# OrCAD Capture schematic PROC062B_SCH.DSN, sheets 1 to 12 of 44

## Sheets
1 44. HARDWARE SCHEMATICS: title: HARDWARE SCHEMATICS; rev: A
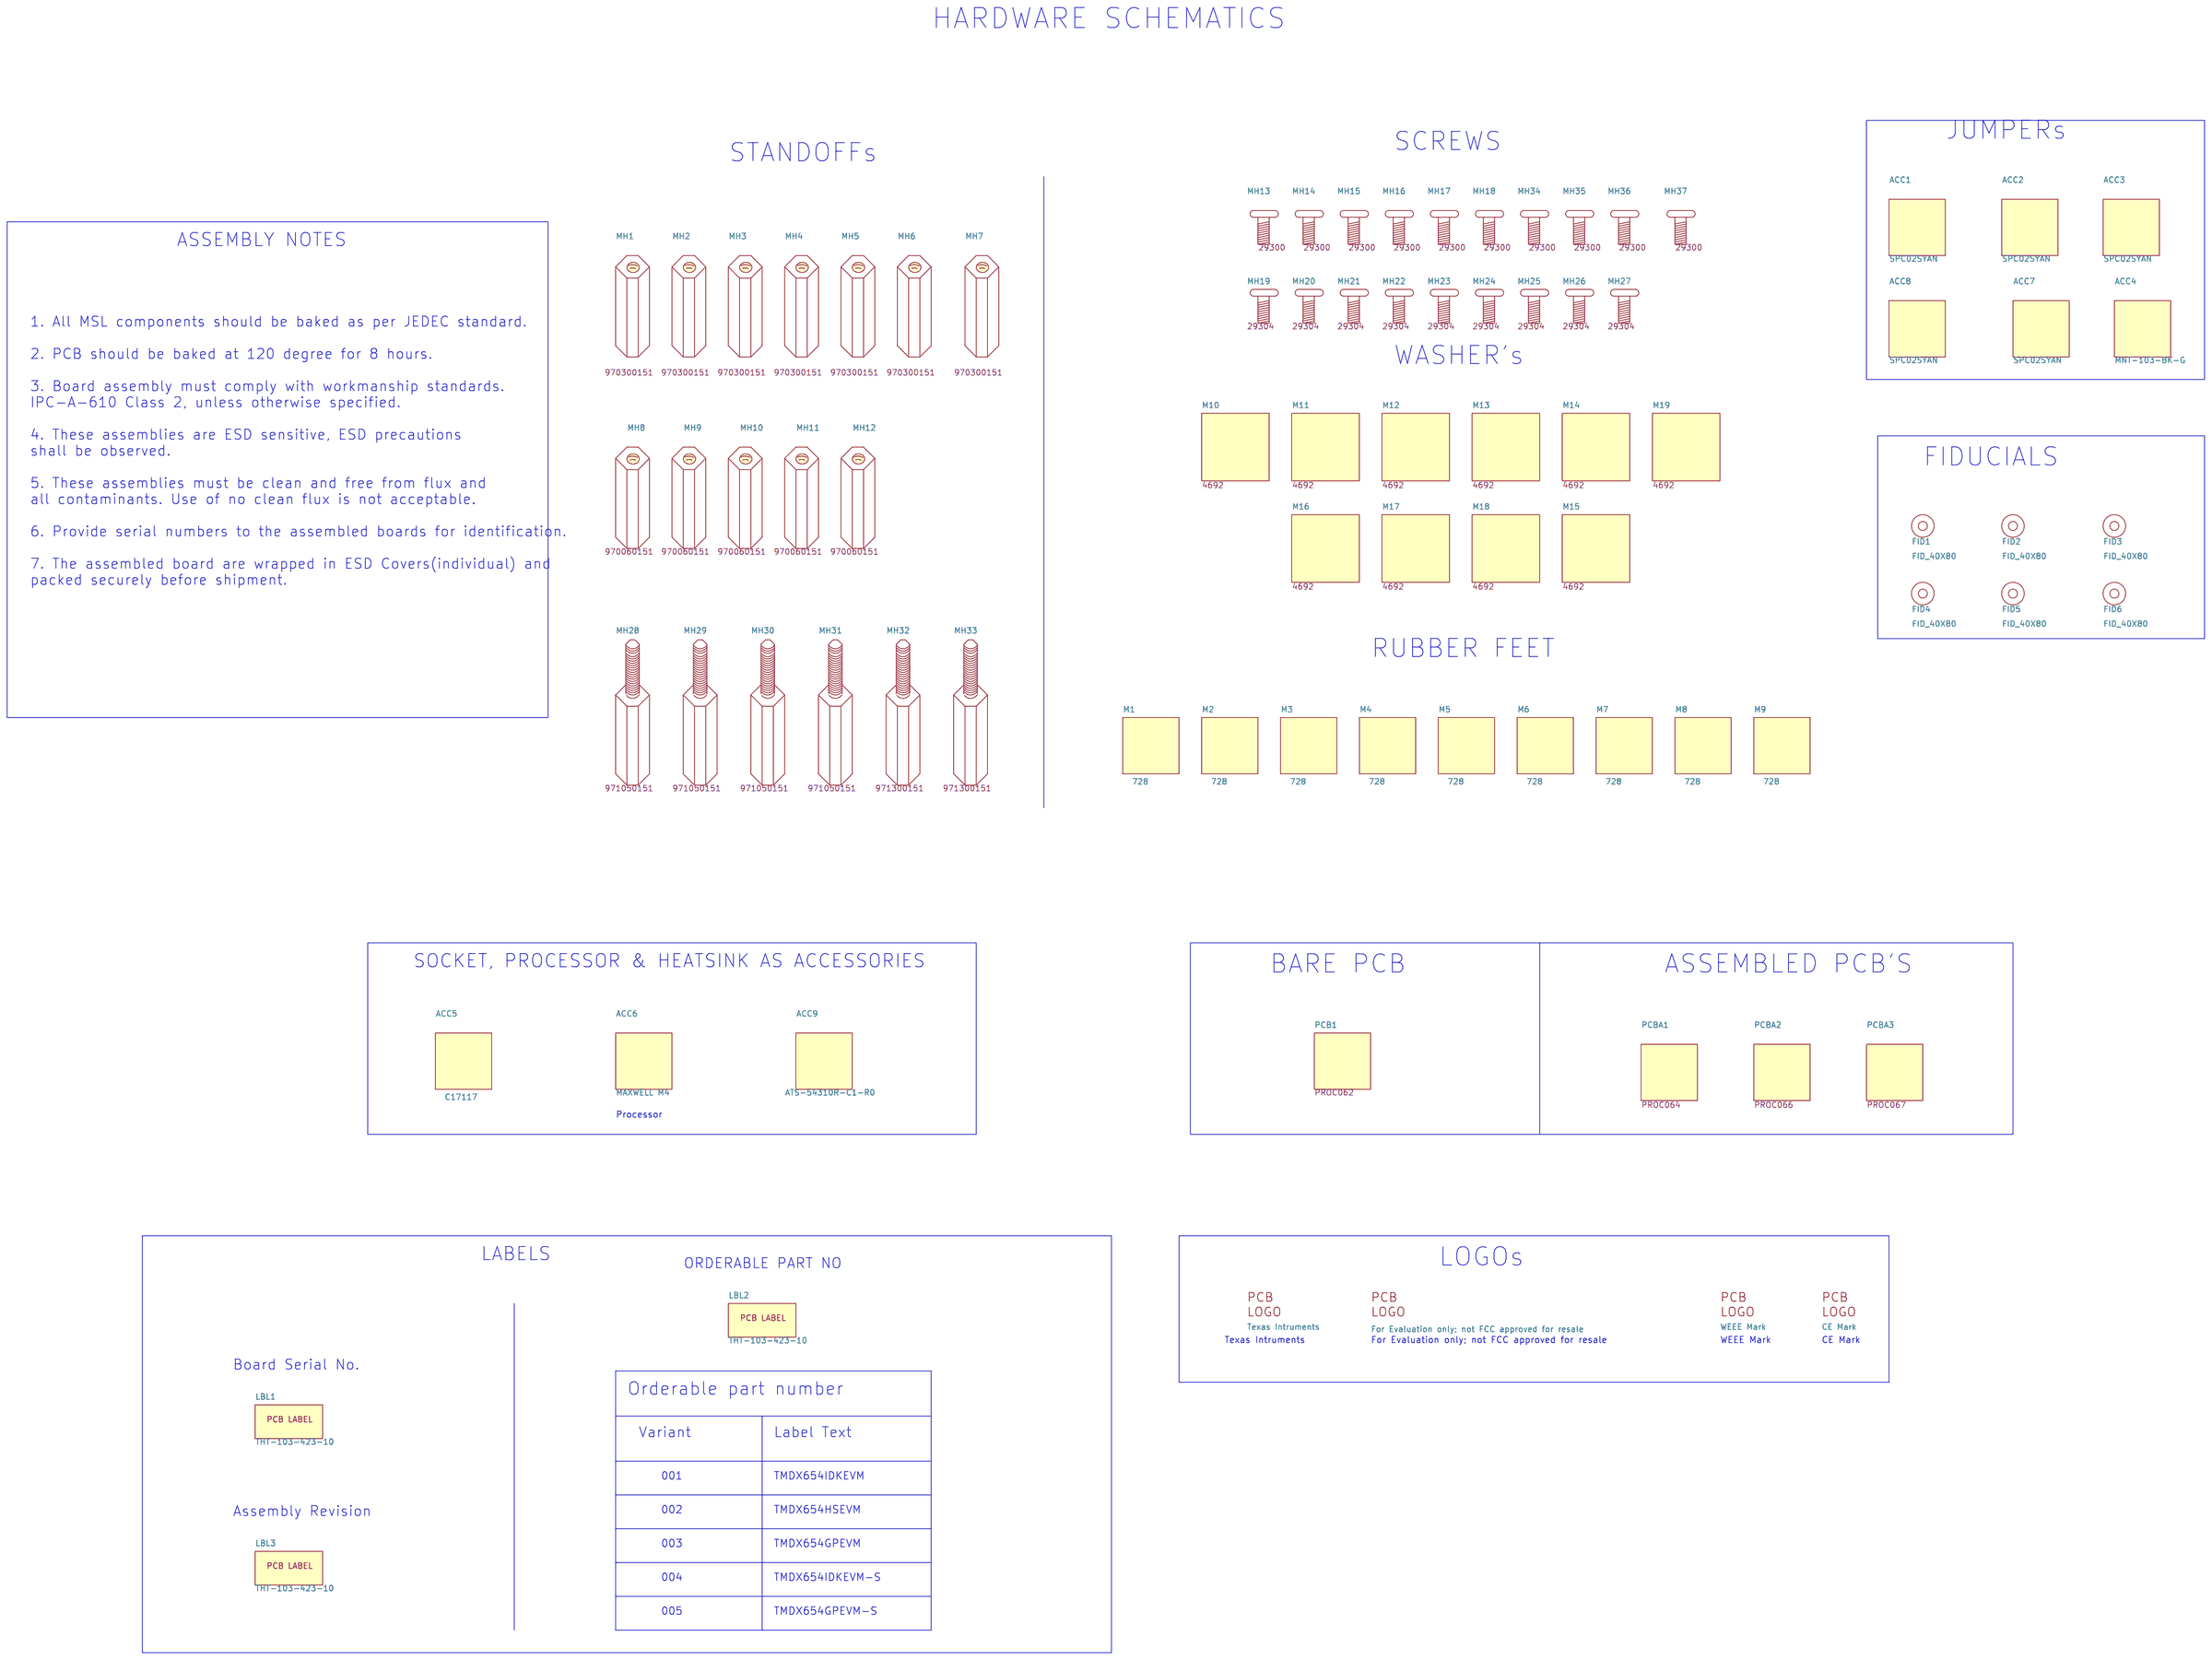
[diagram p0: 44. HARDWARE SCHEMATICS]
2 07. GPIO MAPPING TABLE: title: GPIO  MAPPING TABLE
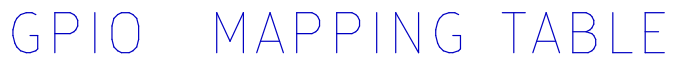
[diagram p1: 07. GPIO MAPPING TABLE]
3 04. BLOCK DIAGRAM_XDS110: title: BLOCK DIAGRAM_XDS110
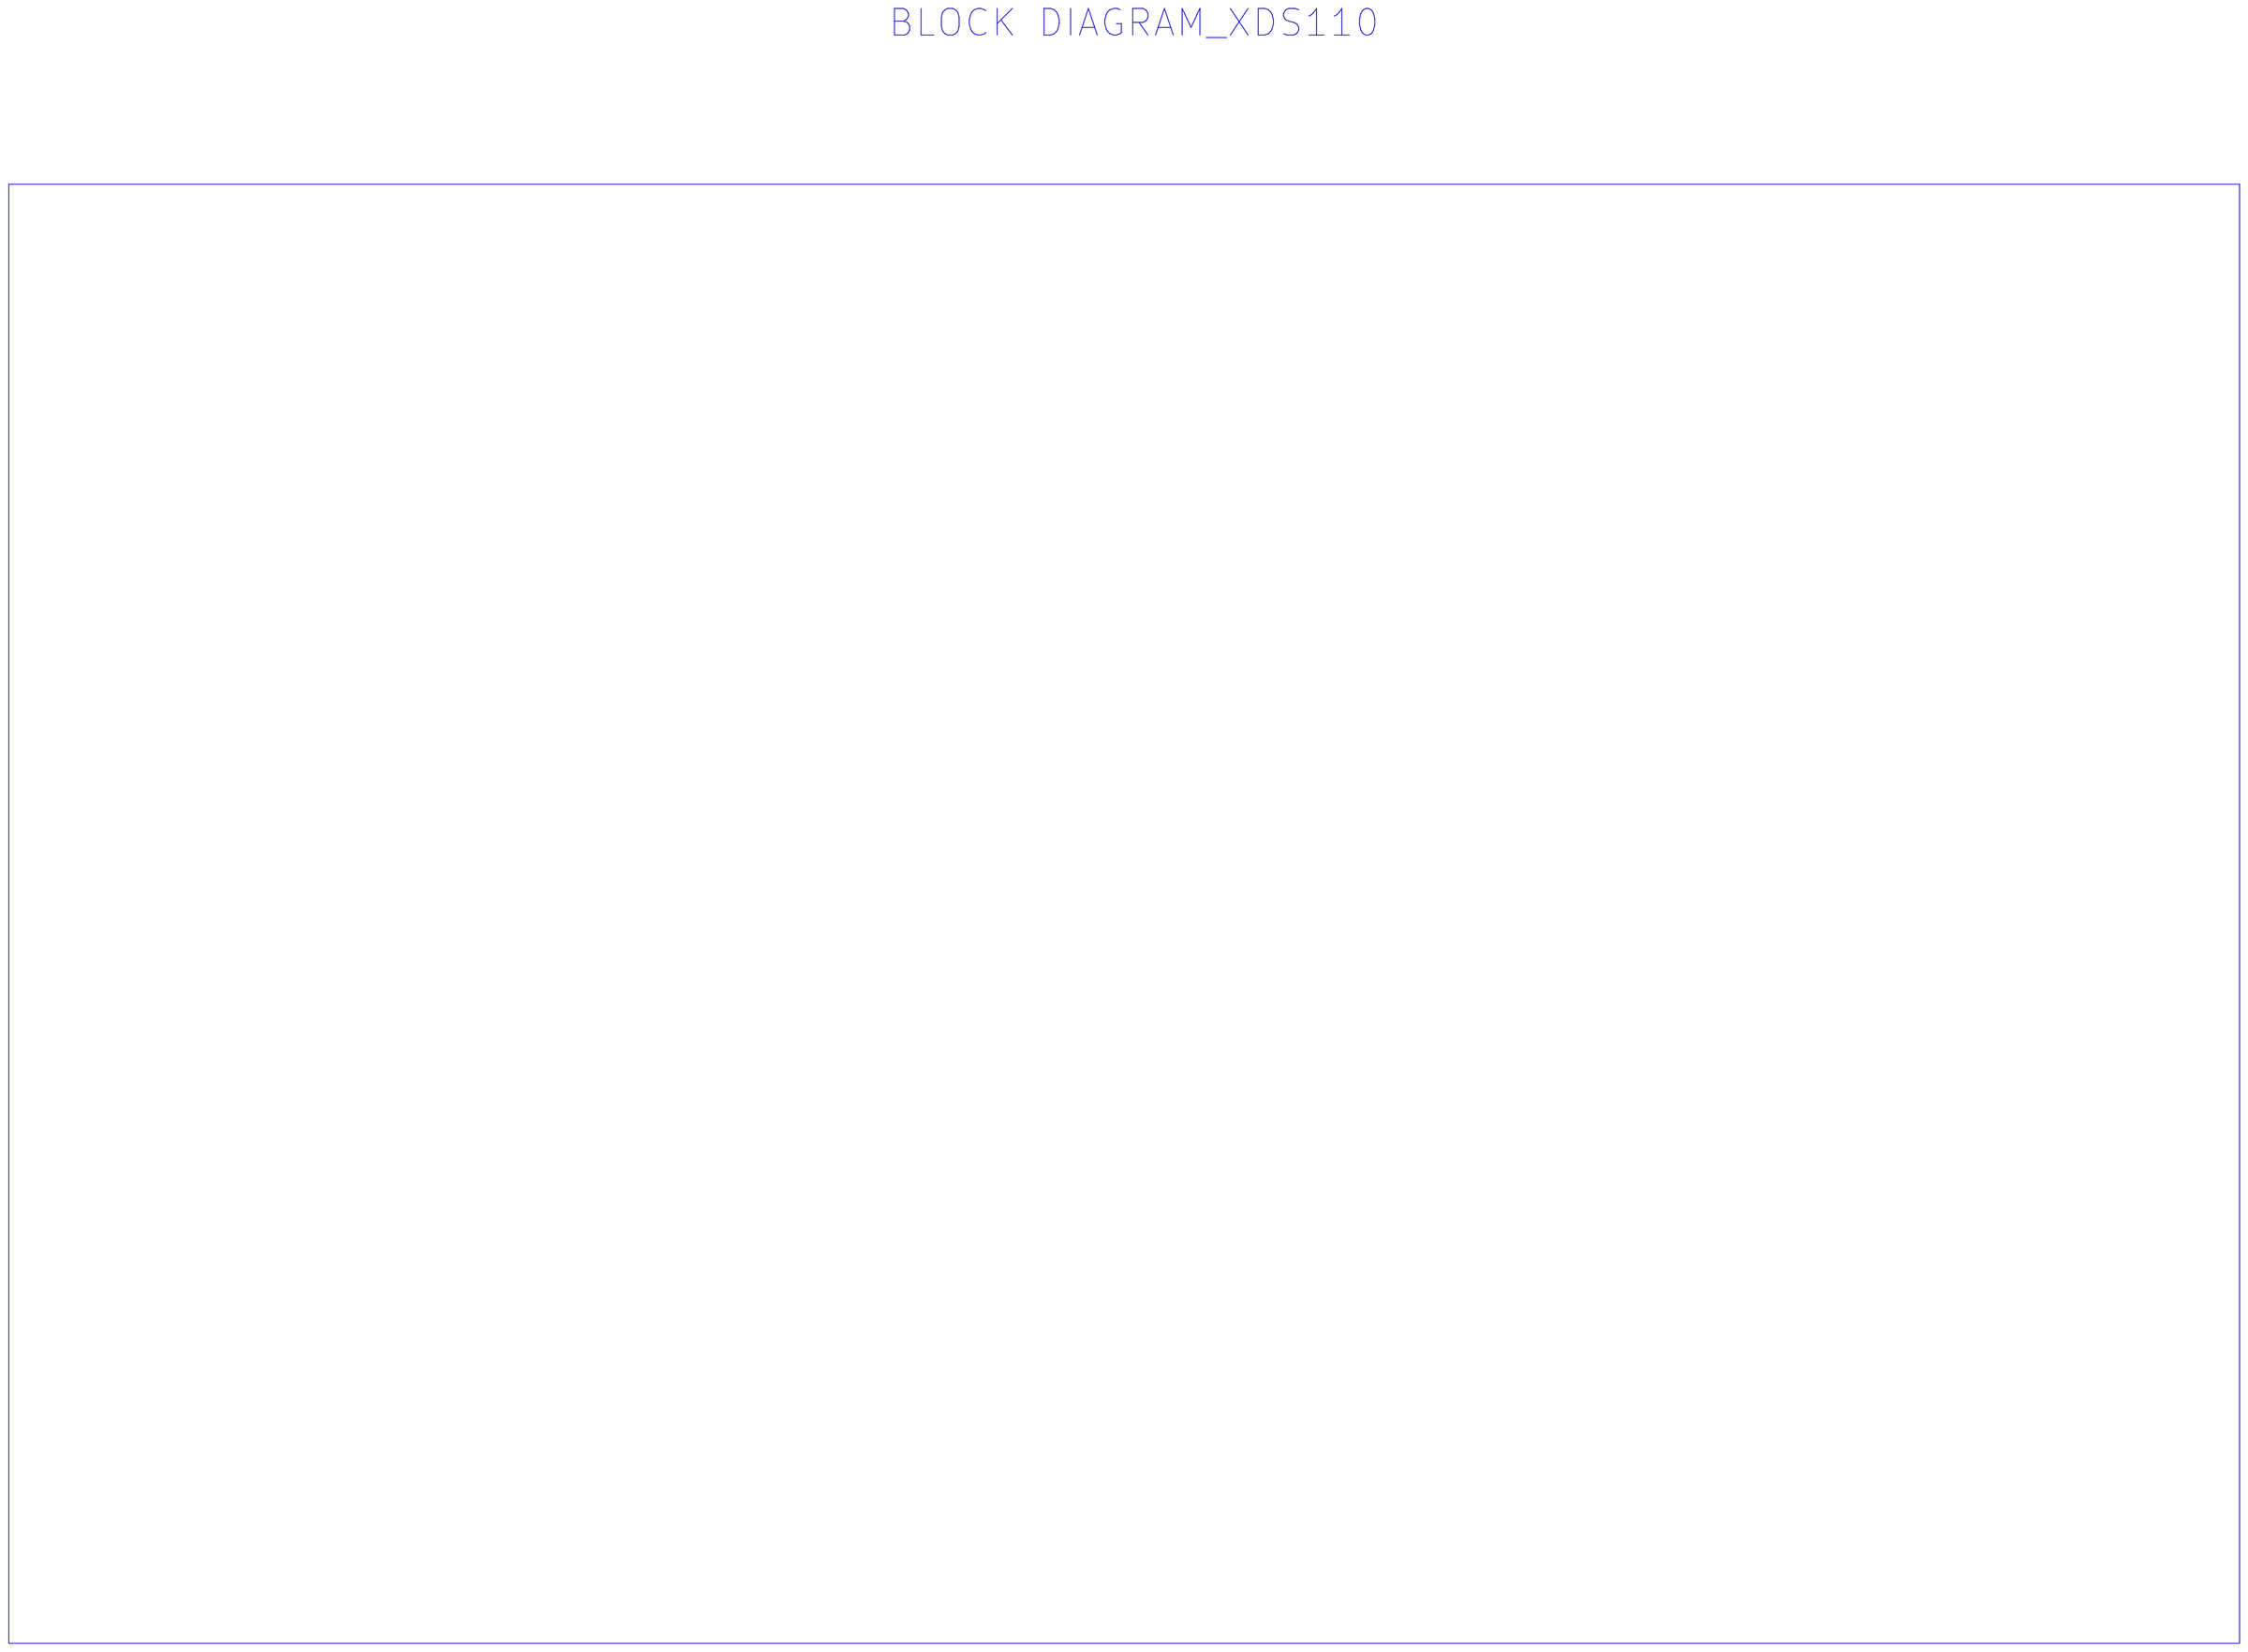
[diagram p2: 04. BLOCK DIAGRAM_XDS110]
4 09. SPI TREE: title: SPI TREE
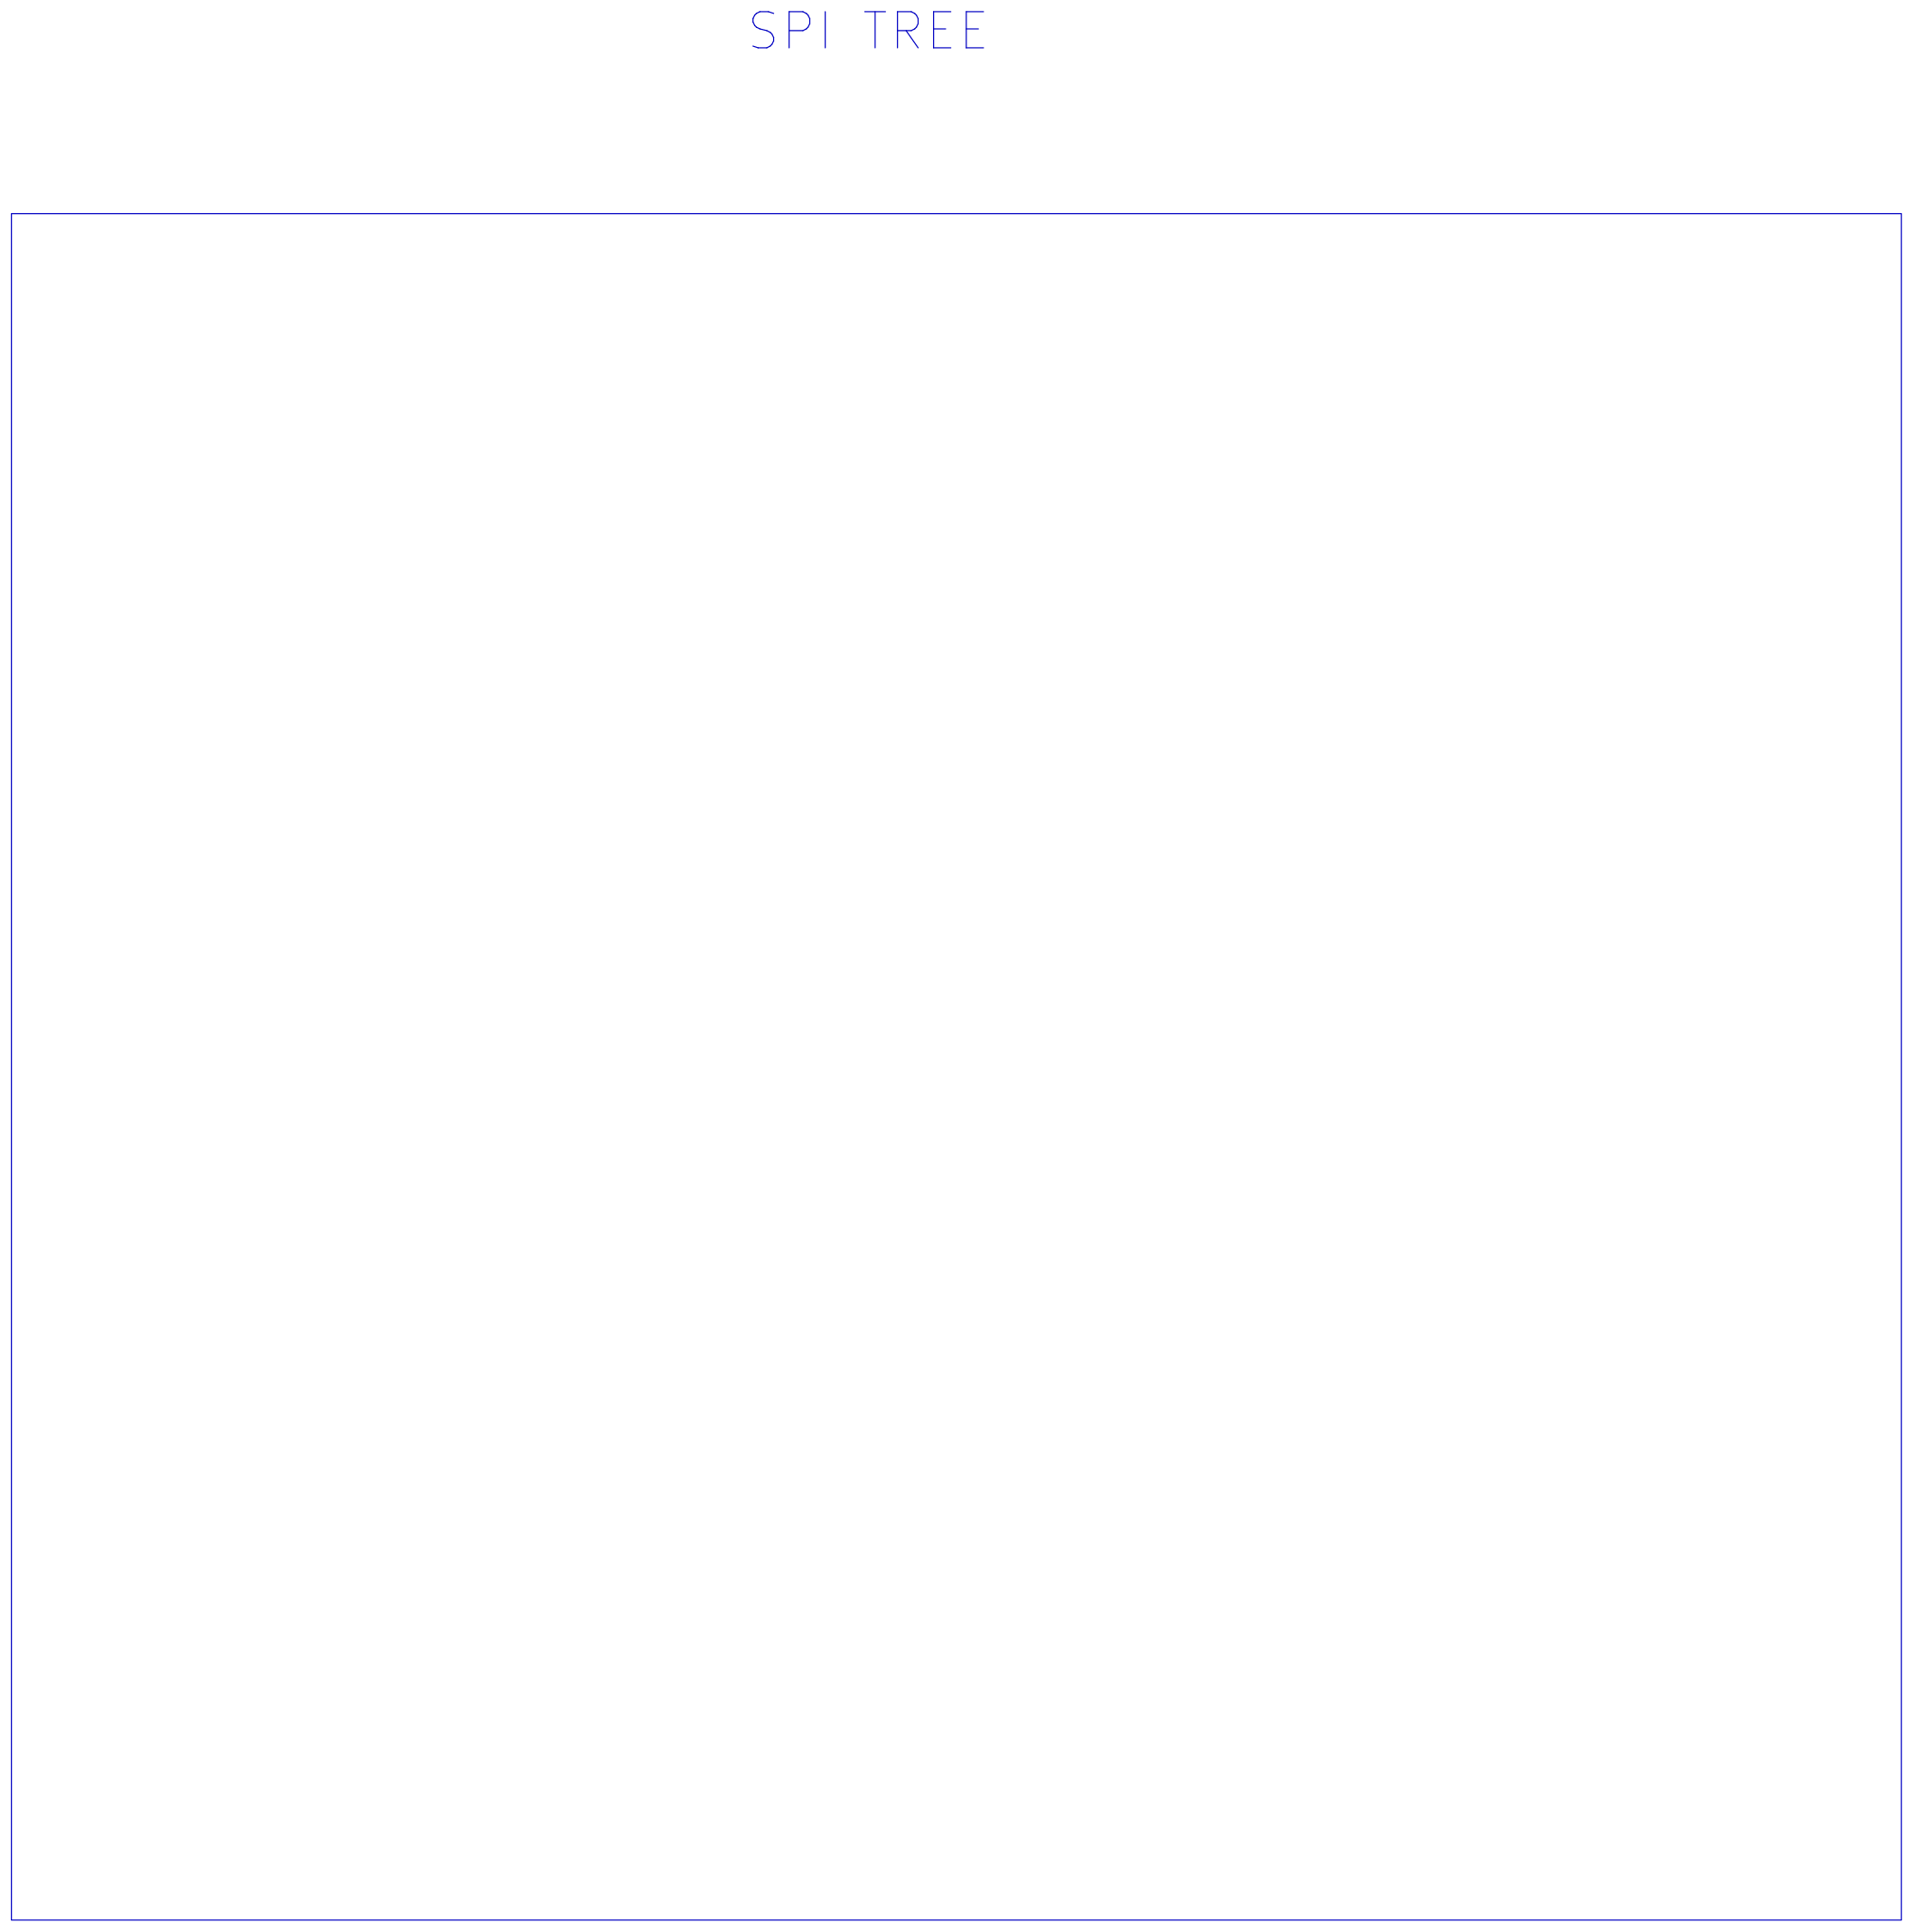
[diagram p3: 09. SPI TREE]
5 08. I2C TREE: title: I2C TREE
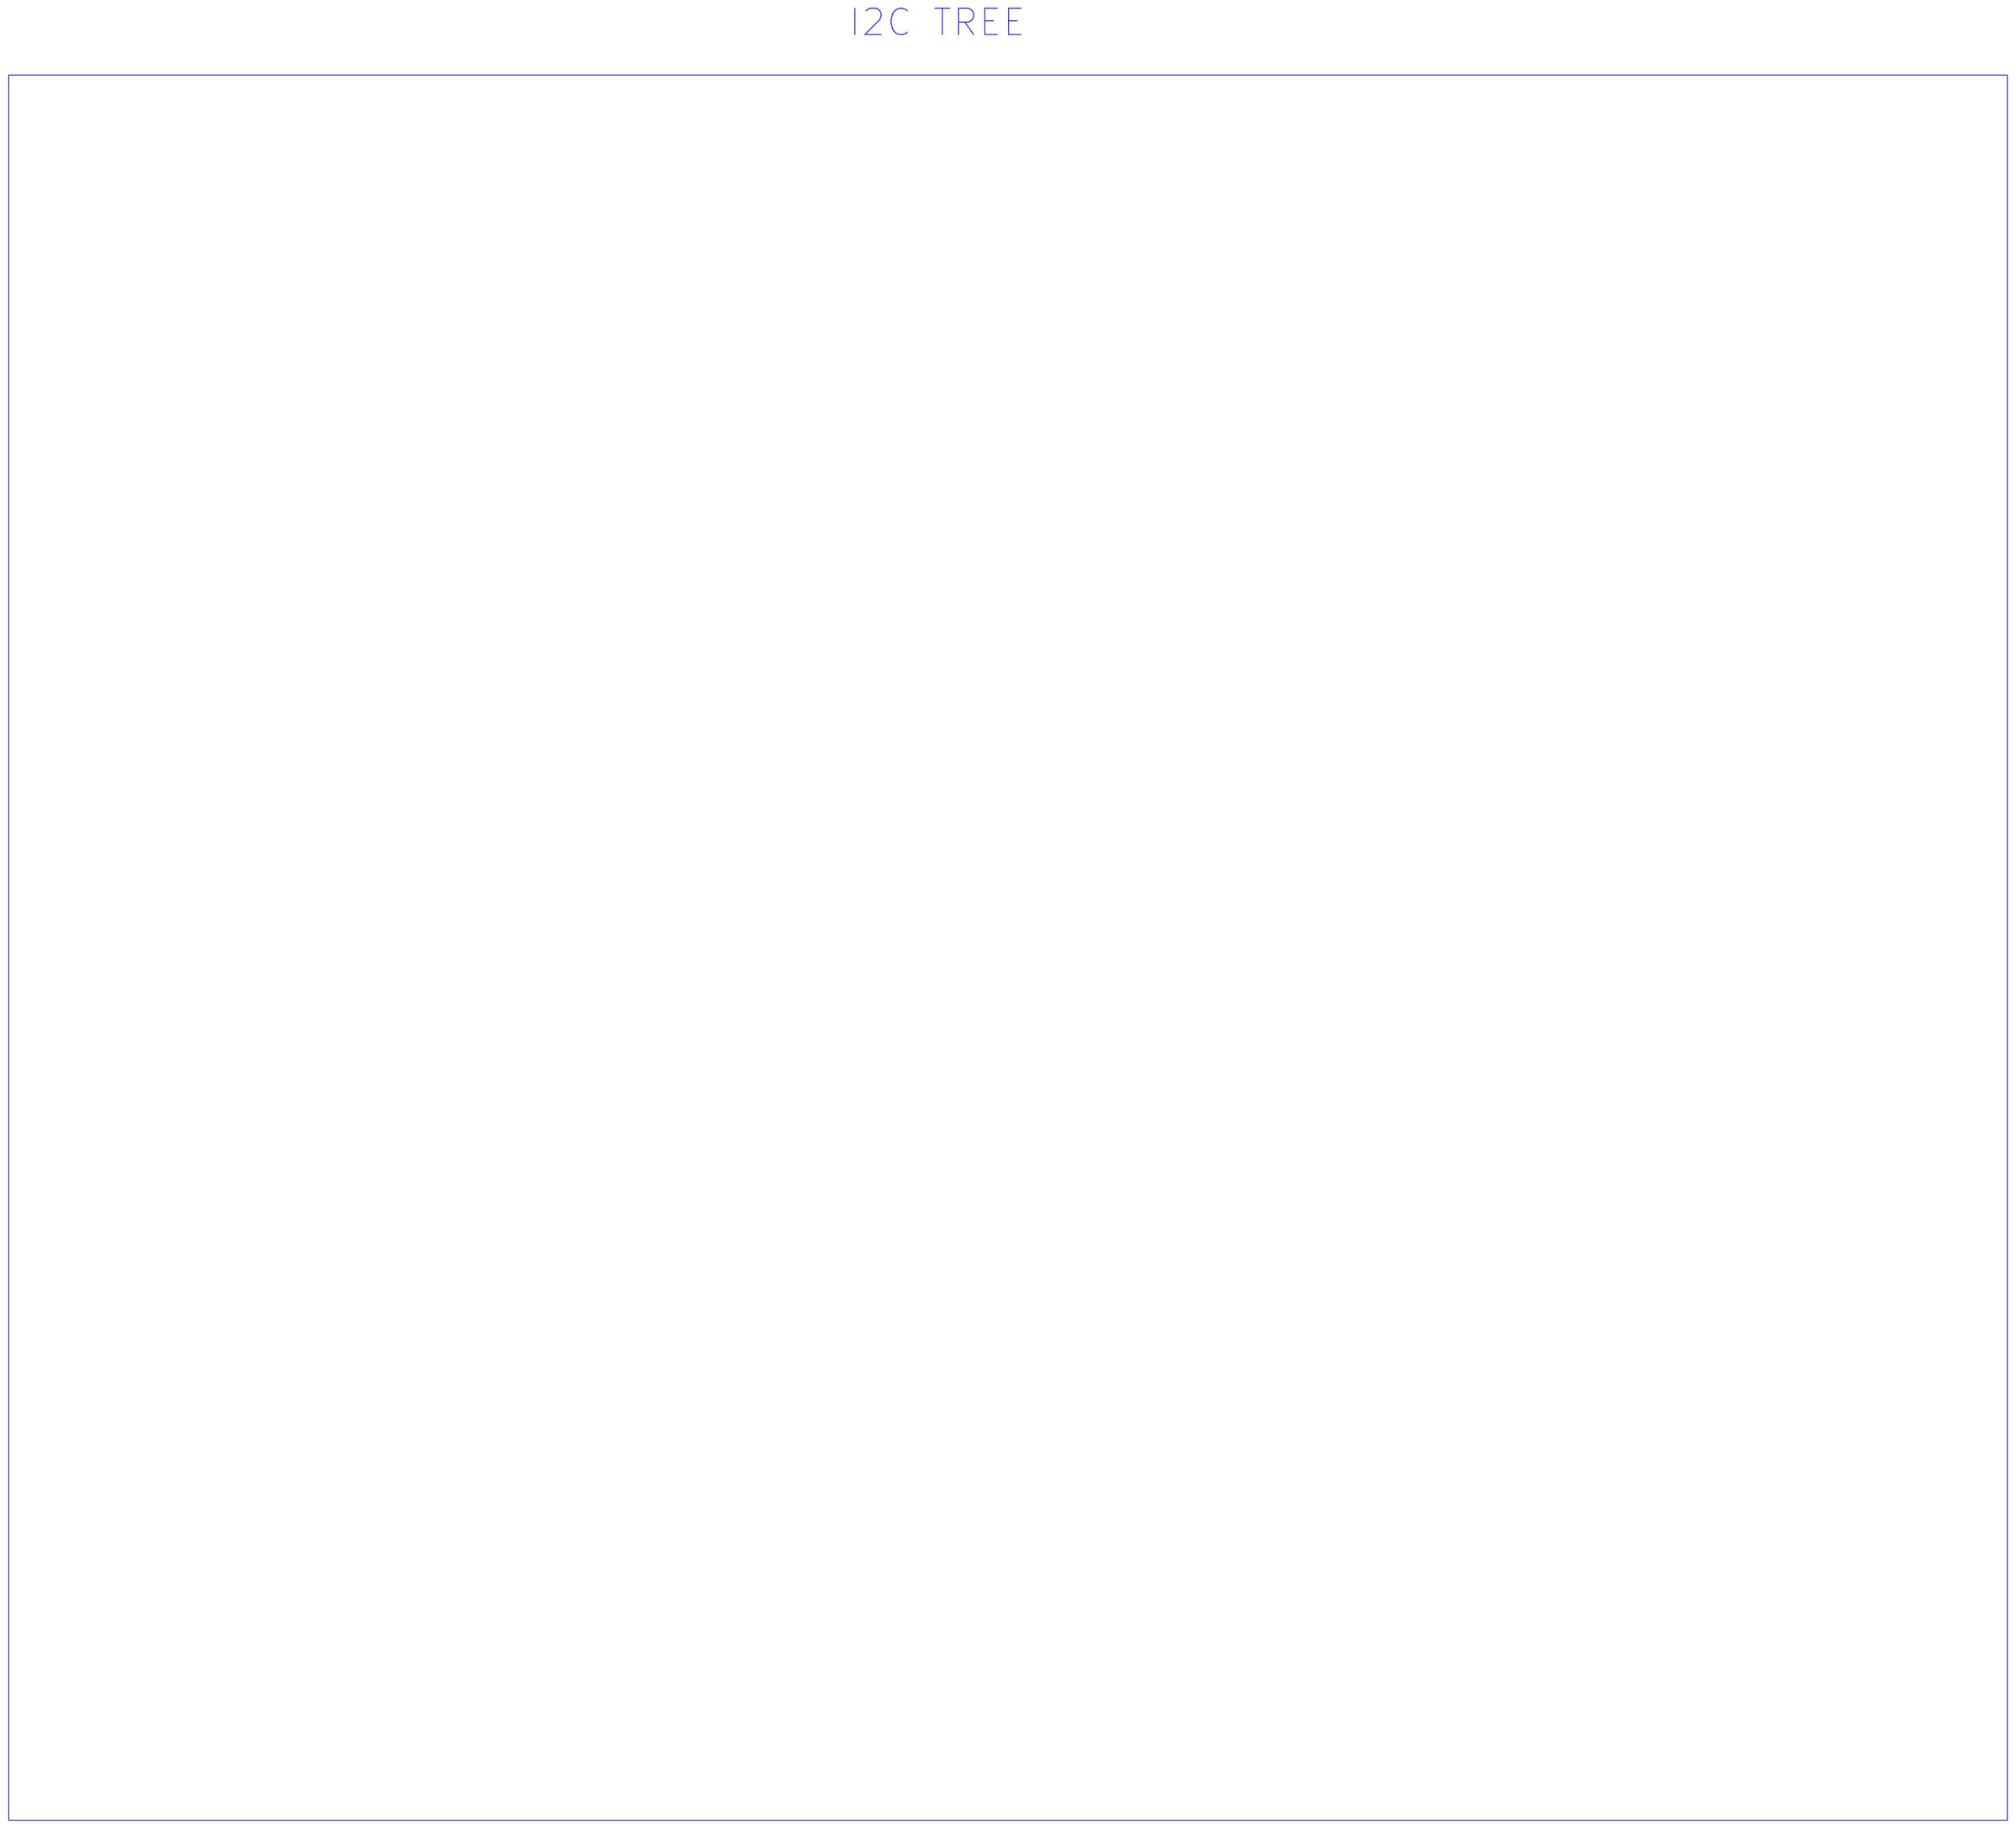
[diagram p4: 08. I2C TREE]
6 06.POWER SEQUENCE: title: POWER SEQUENCE
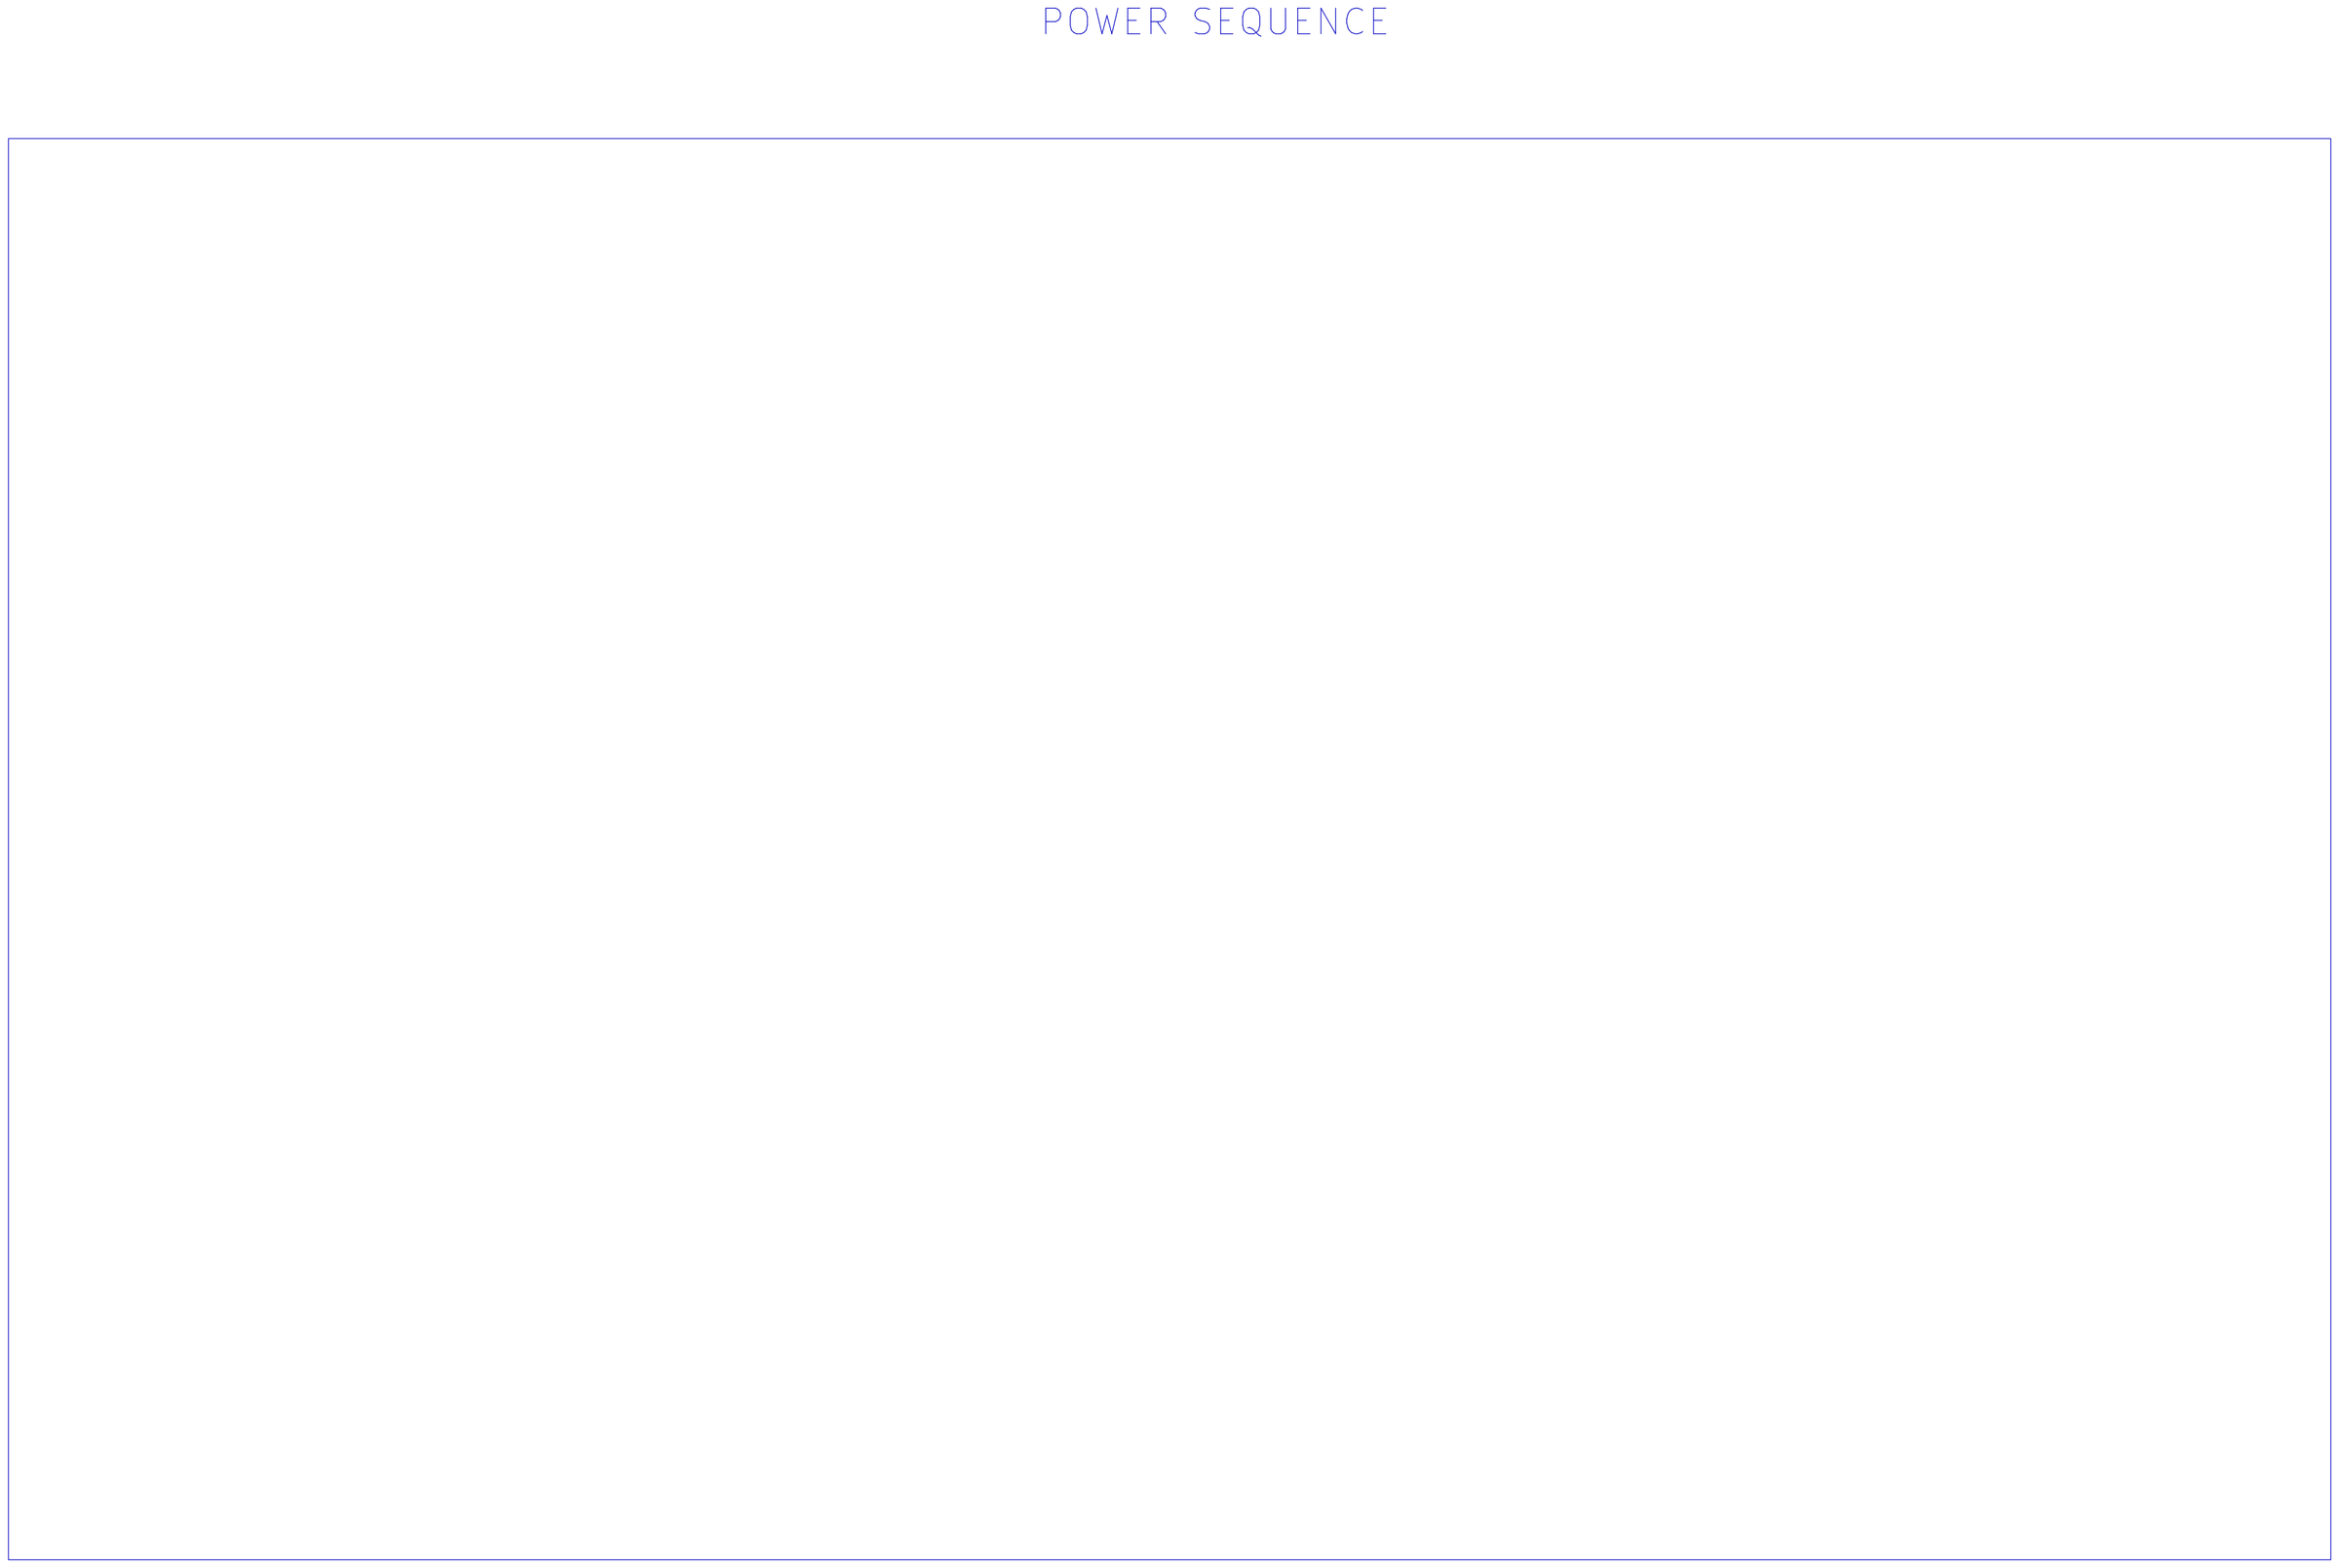
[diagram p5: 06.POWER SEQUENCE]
7 05. POWER FLOW DIAGRAM: title: POWER FLOW DIAGRAM
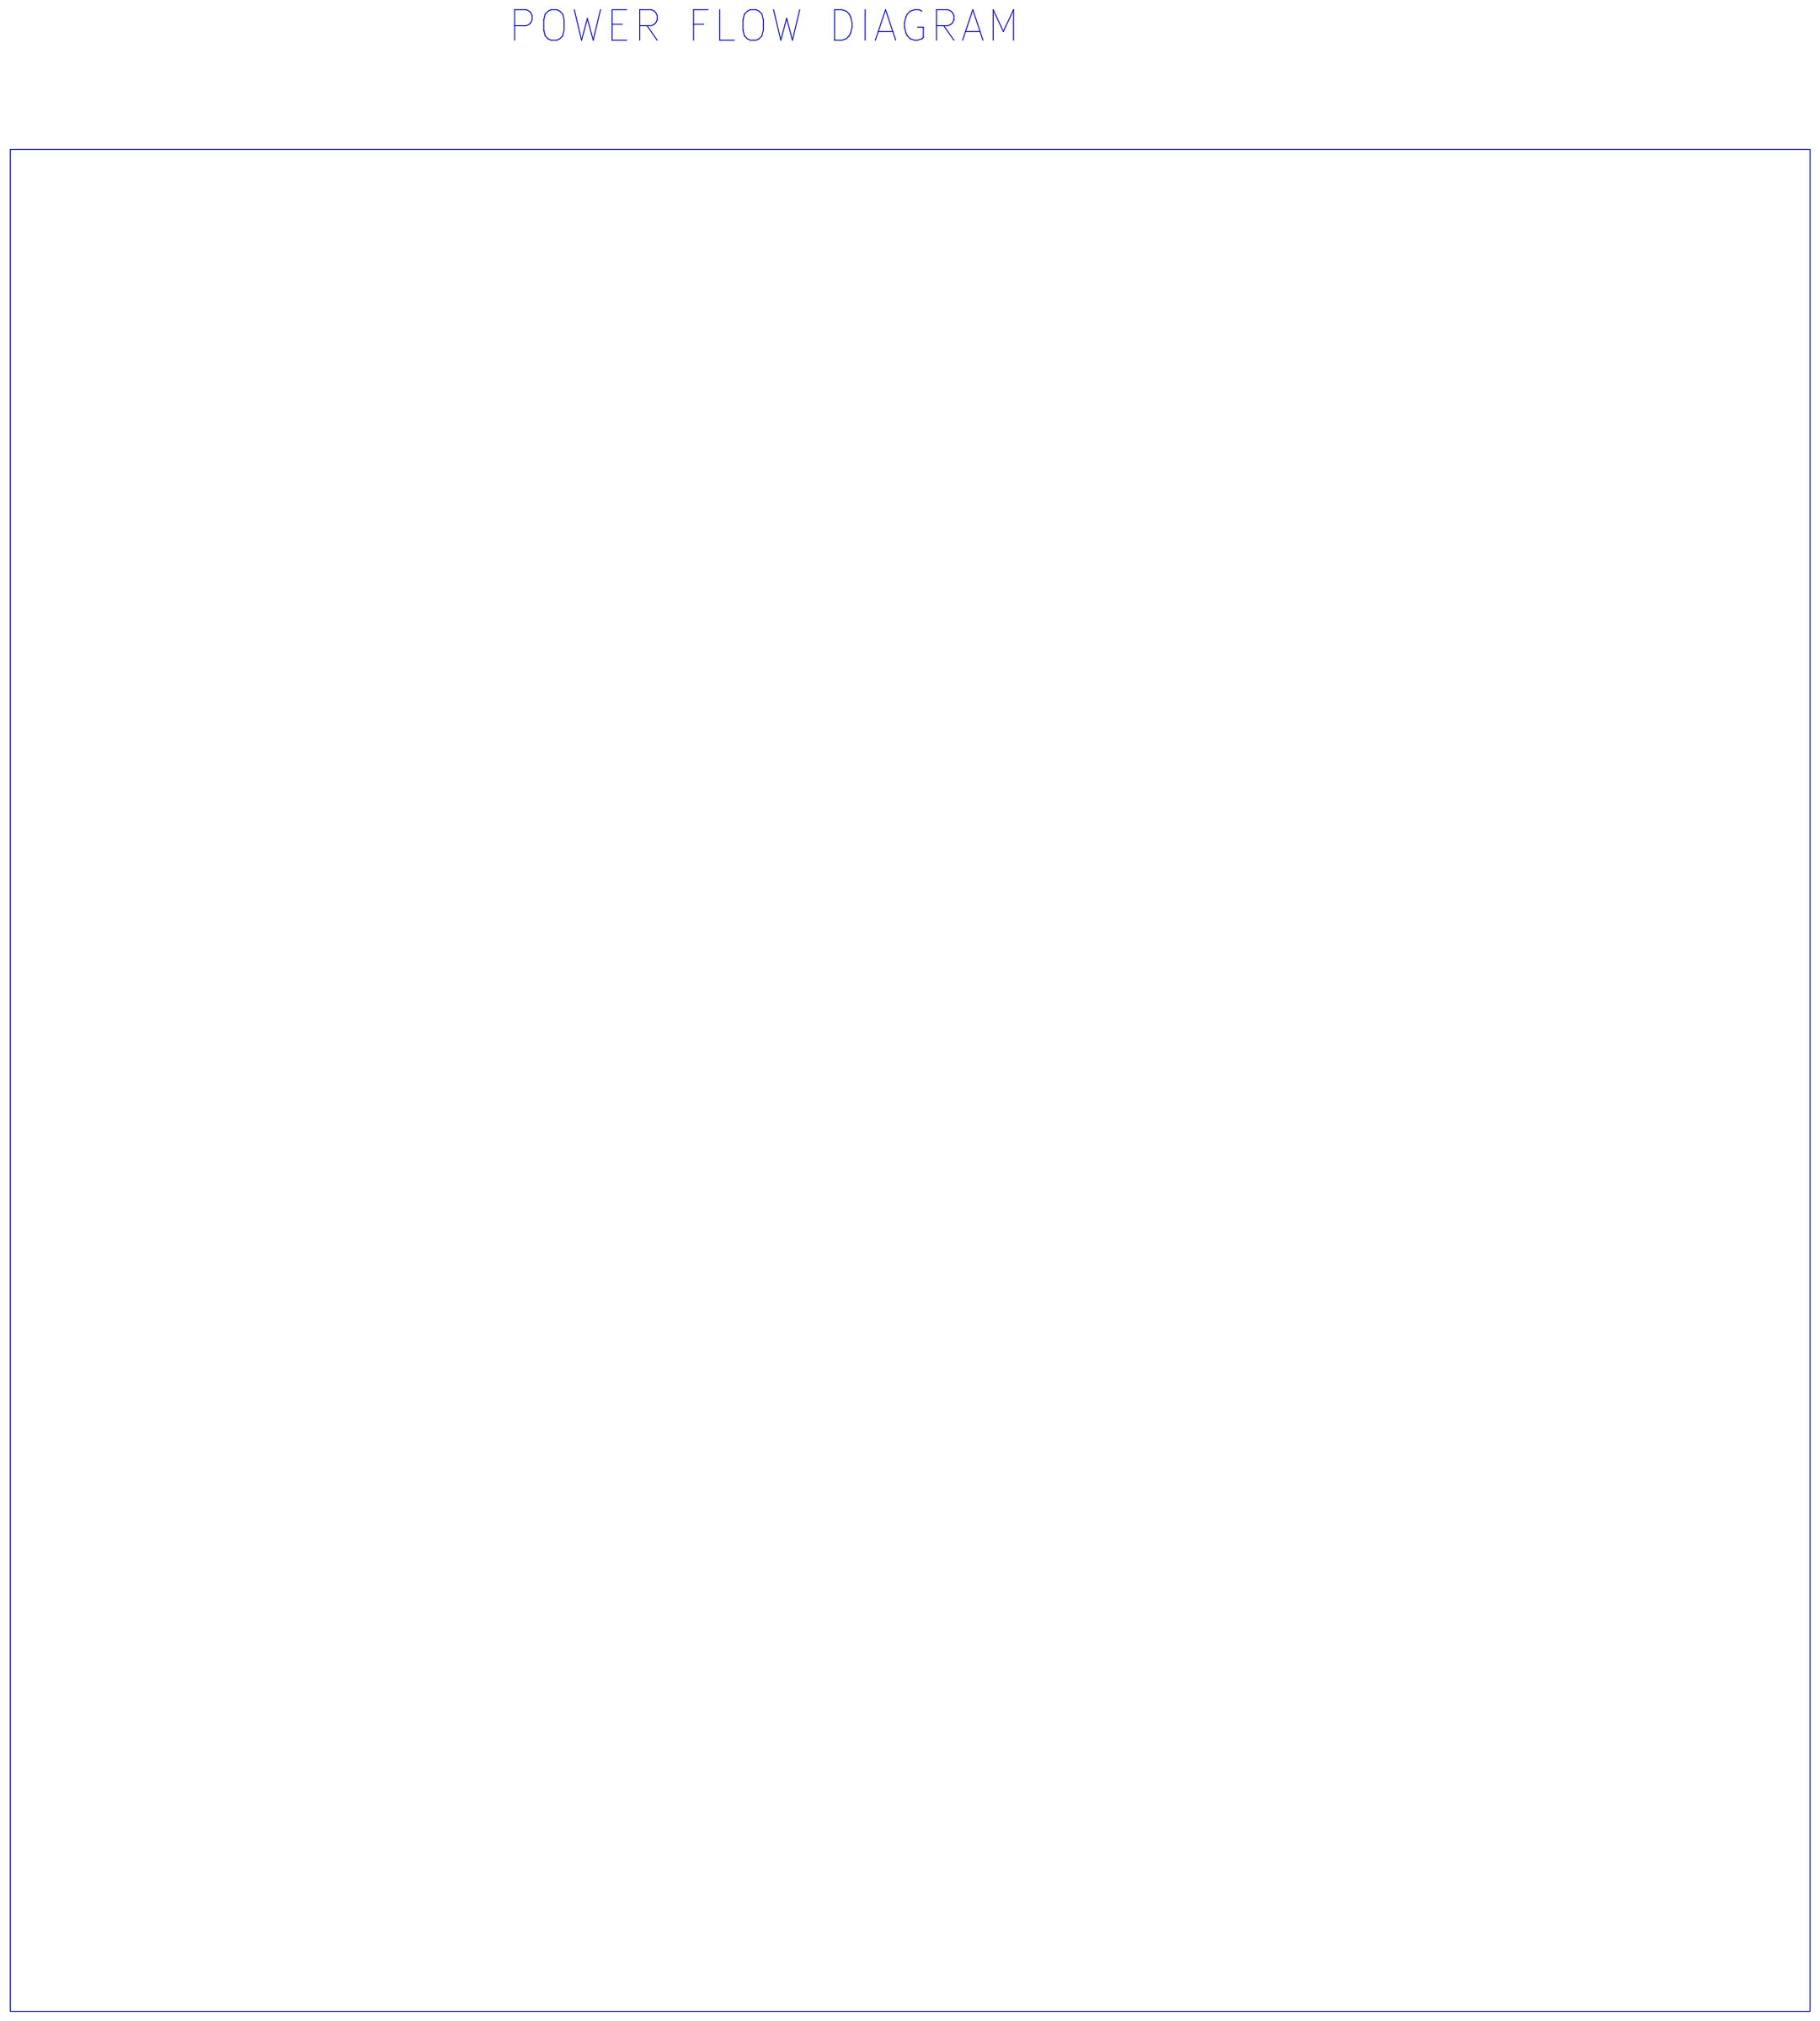
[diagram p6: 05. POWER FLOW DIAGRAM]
8 03.BLOCK_DIAGRAM_CP_BOARD: title: BLOCK DIAGRAM_CP BOARD
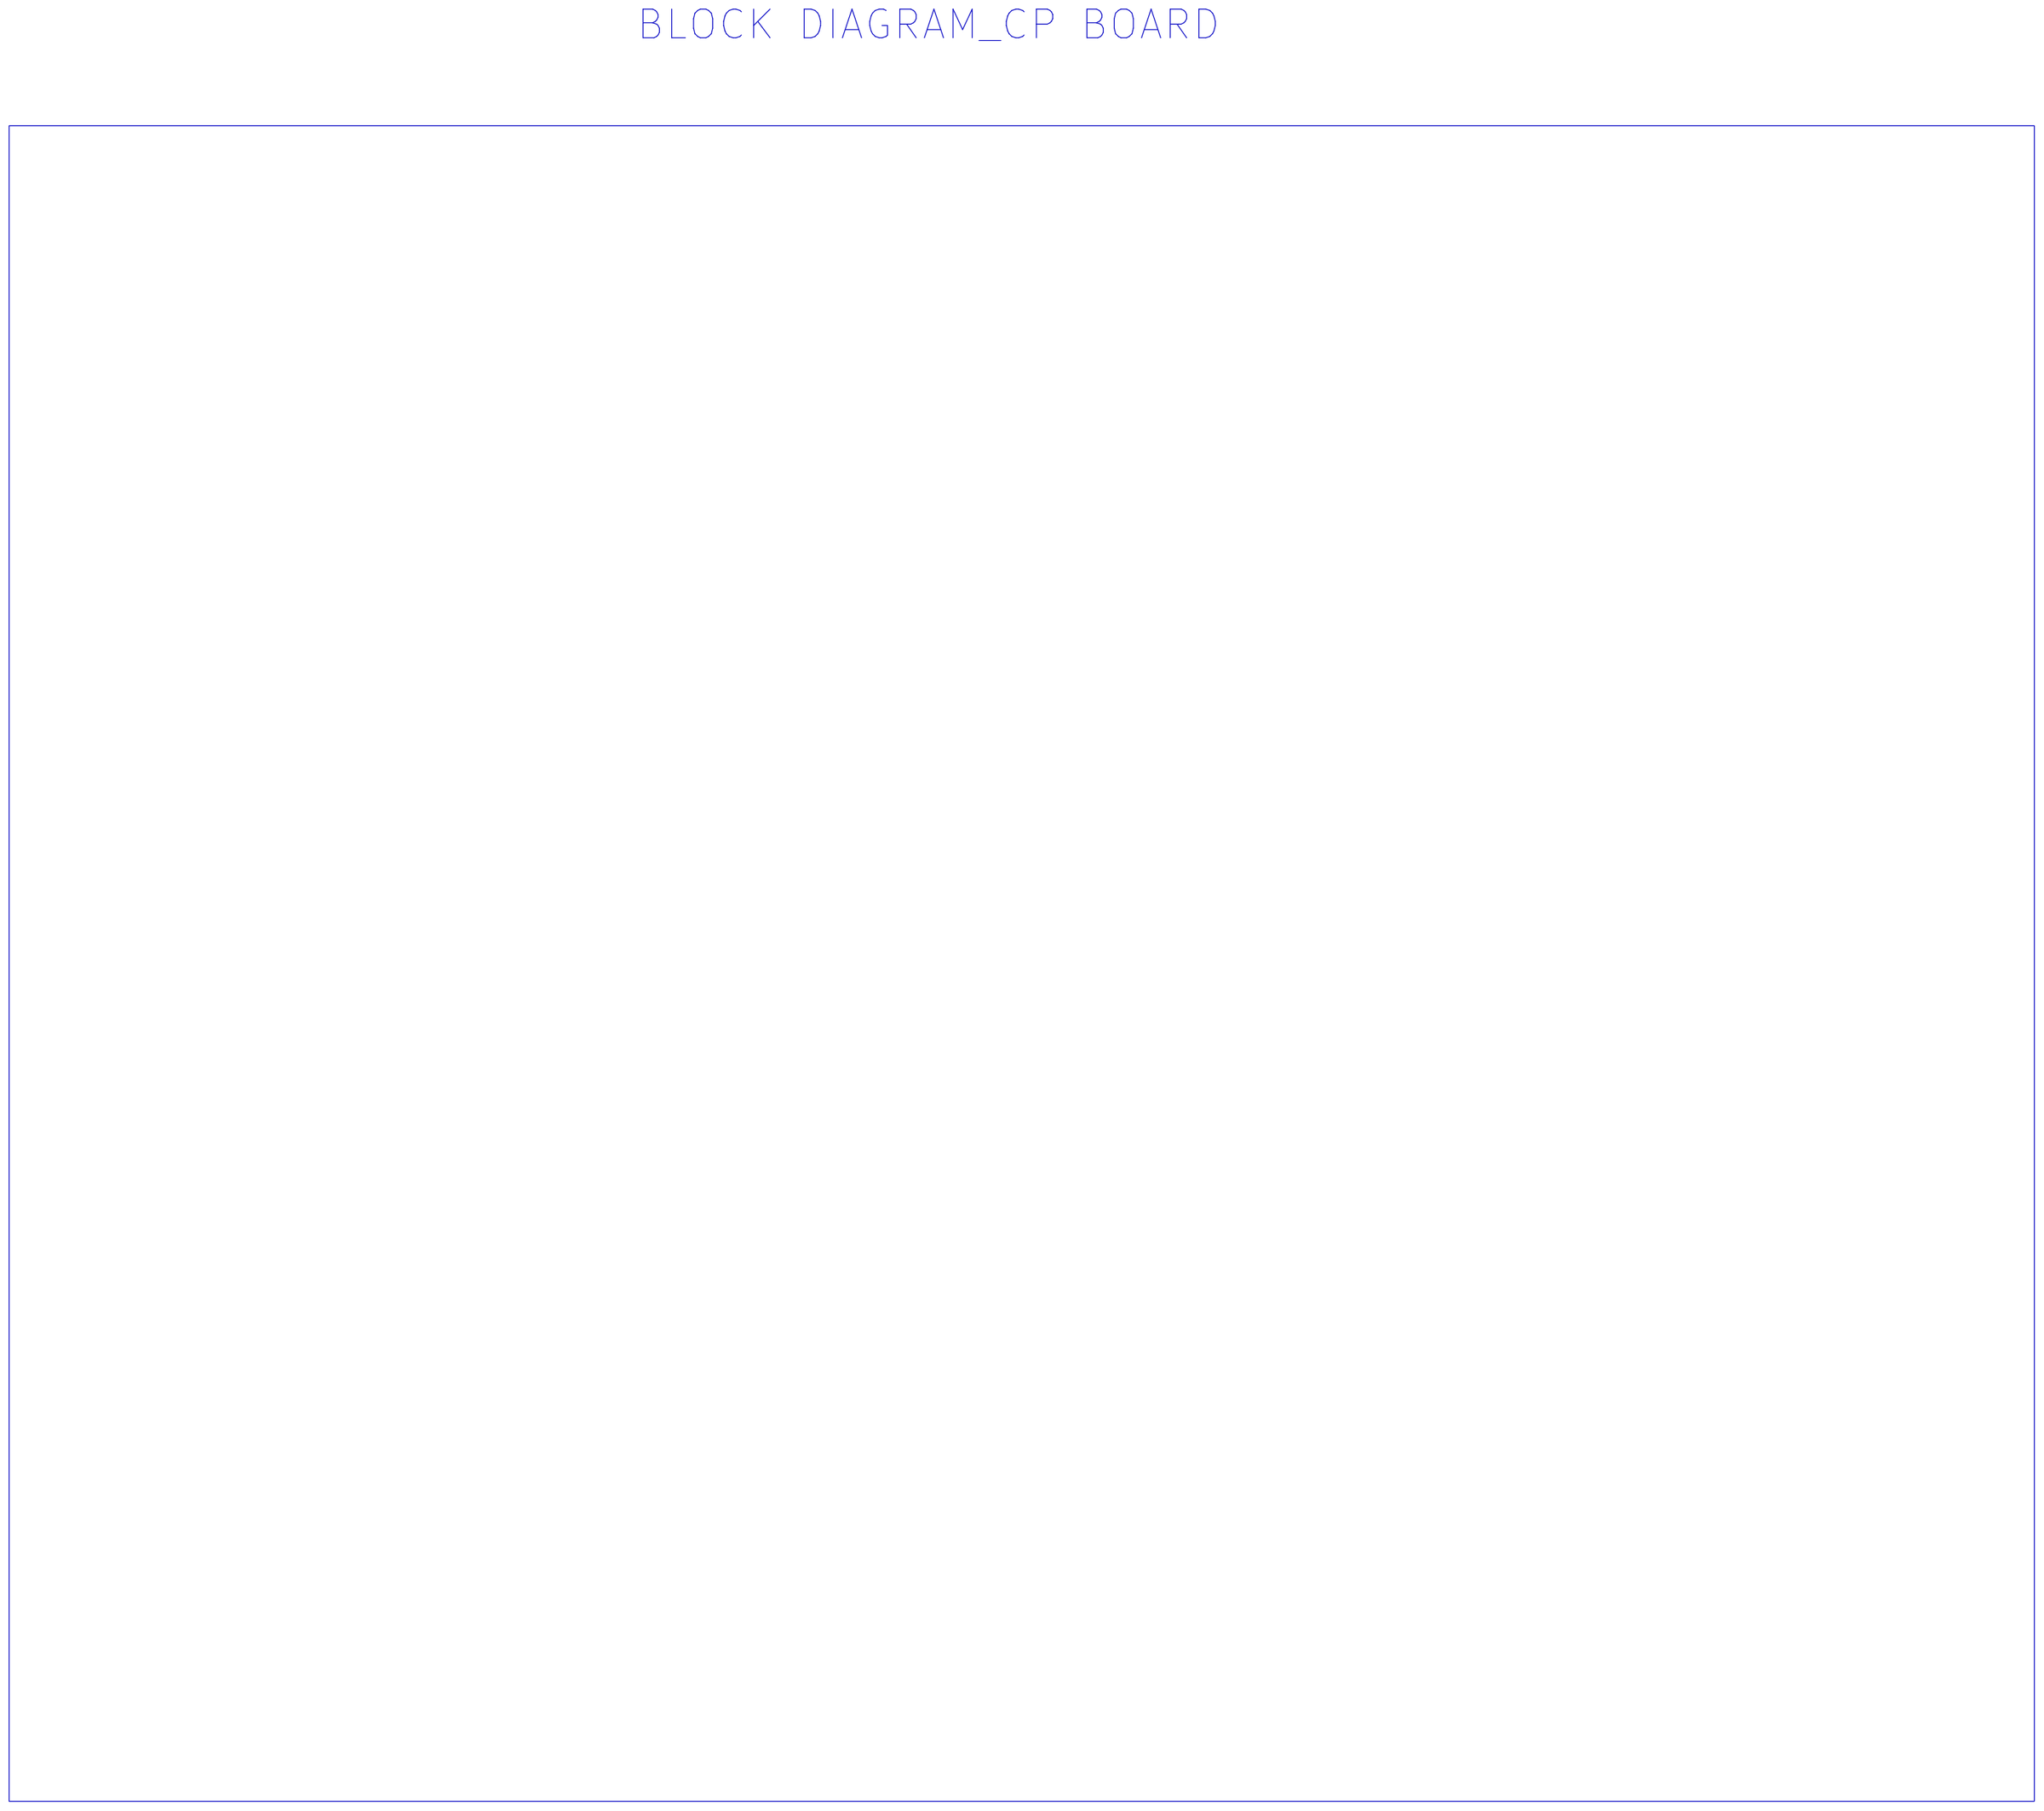
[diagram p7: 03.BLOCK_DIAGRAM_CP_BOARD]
9 01. TABLE OF CONTENTS: title: TABLE OF CONTENTS
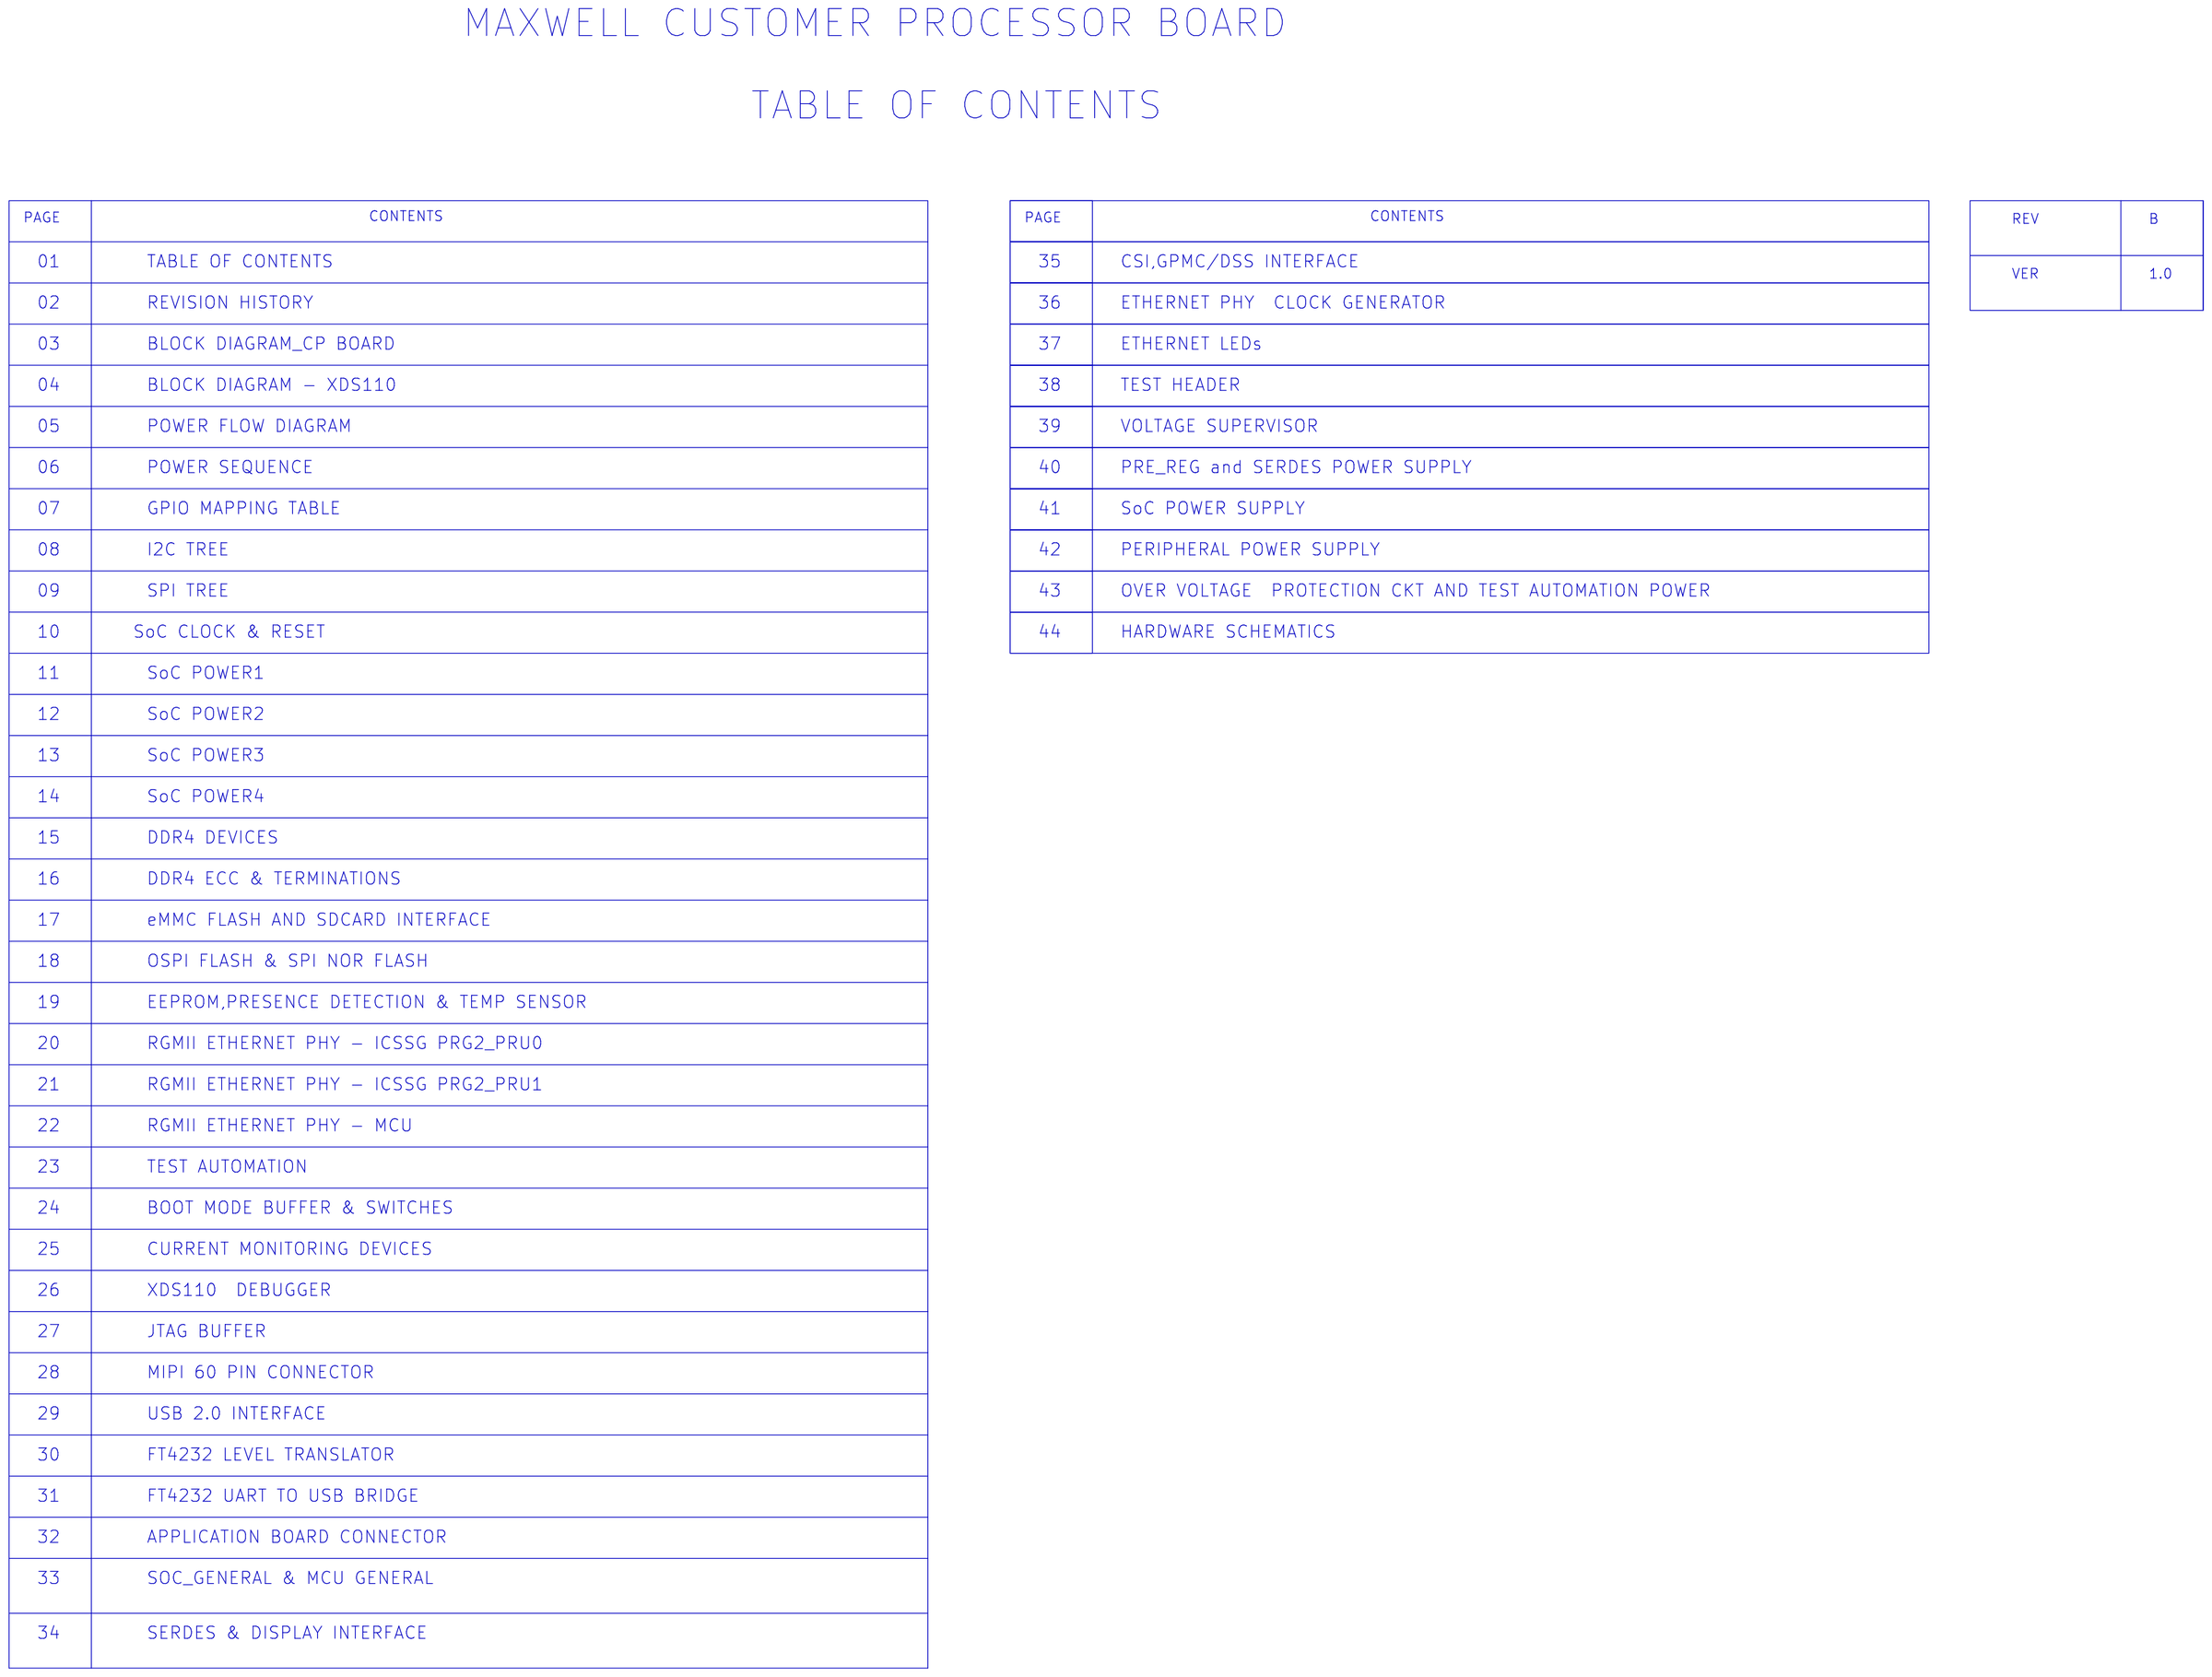
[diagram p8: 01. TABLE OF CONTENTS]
10 02. REVISION HISTORY: title: REVISION HISTORY
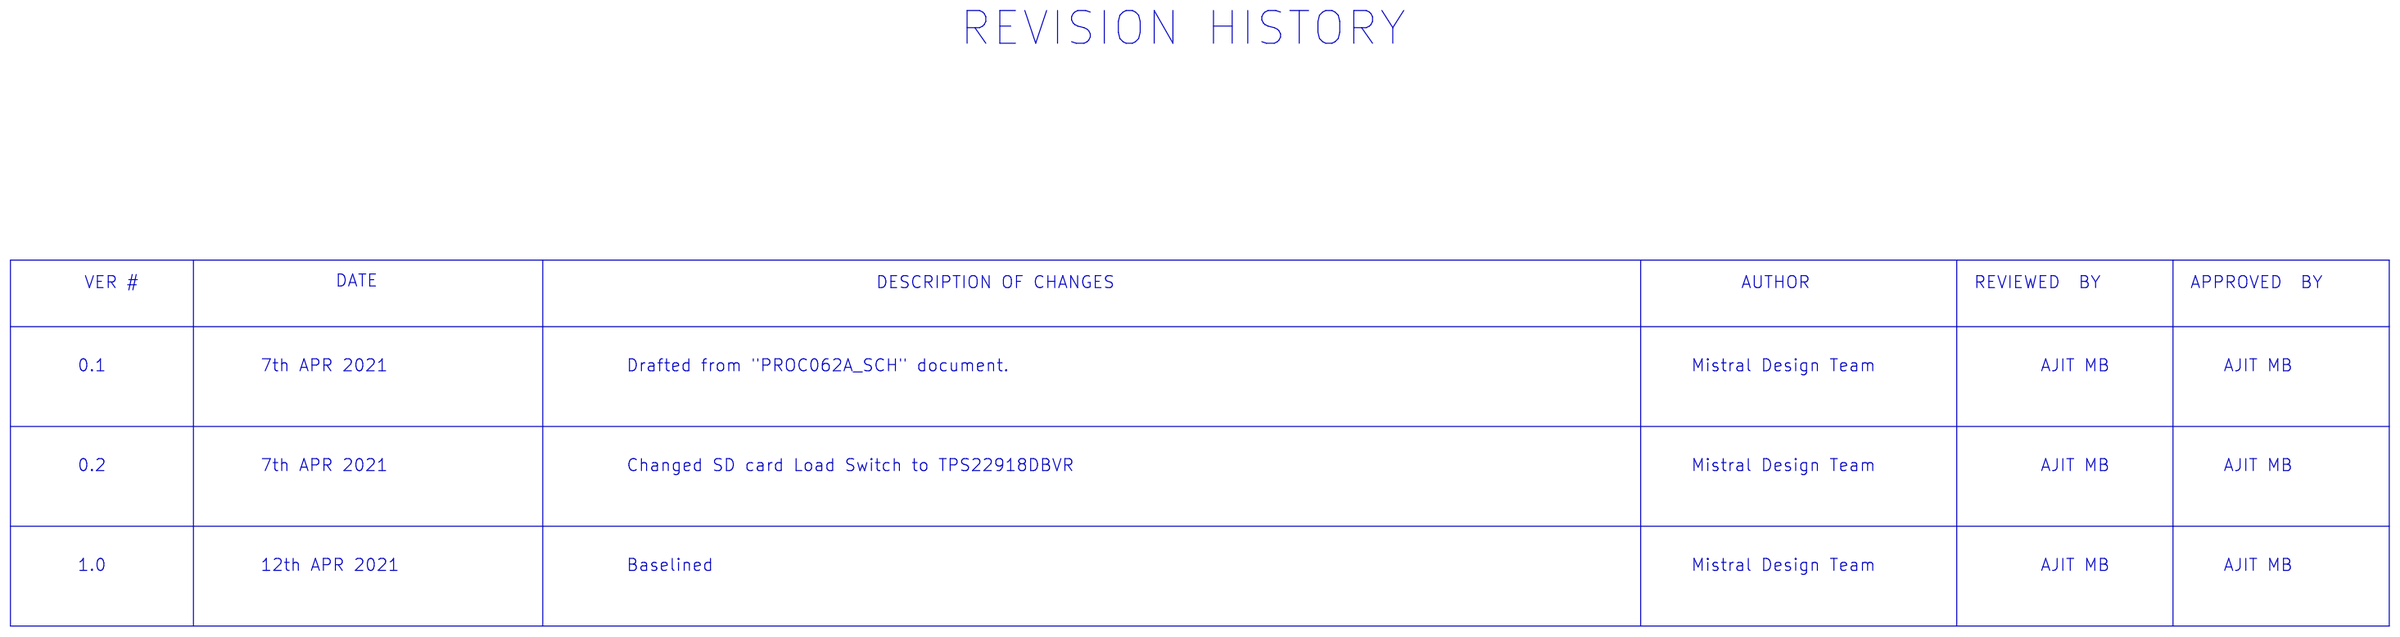
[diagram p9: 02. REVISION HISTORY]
11 10. SoC CLOCK & RESET: size C; title: SoC CLOCK & RESET
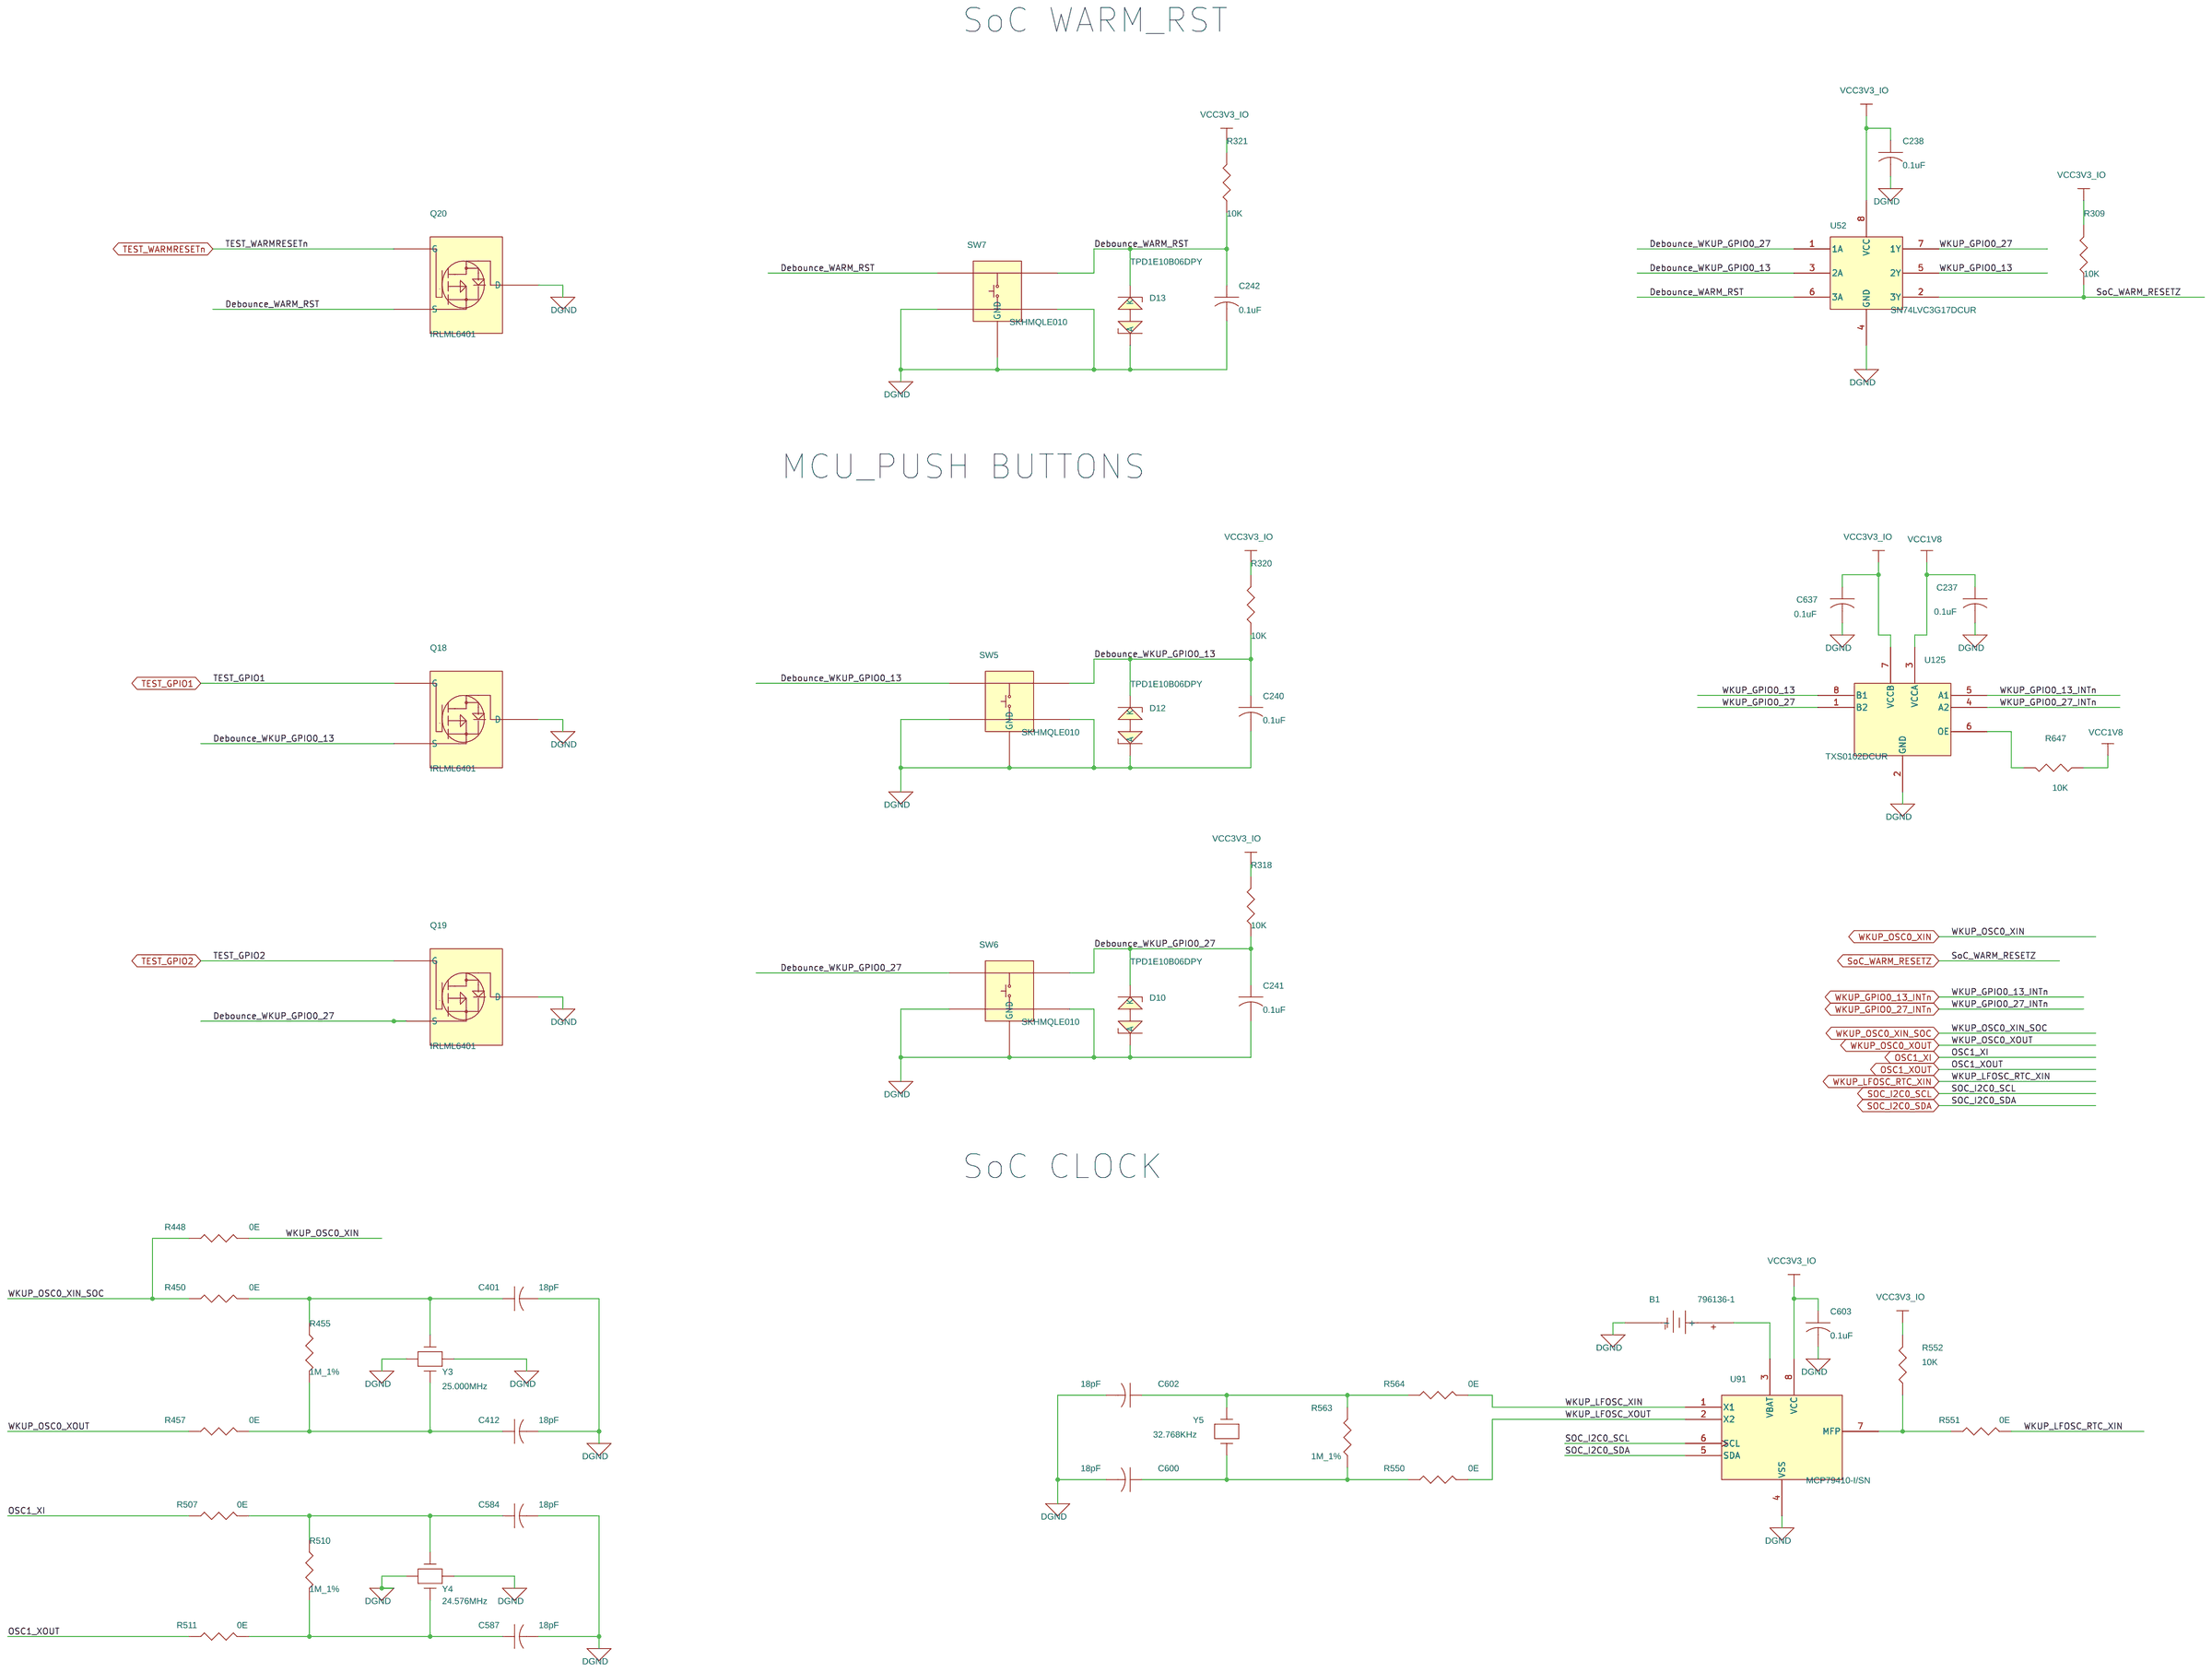
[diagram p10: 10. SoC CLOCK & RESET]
12 11. SoC POWER1: size C; title: SoC POWER1
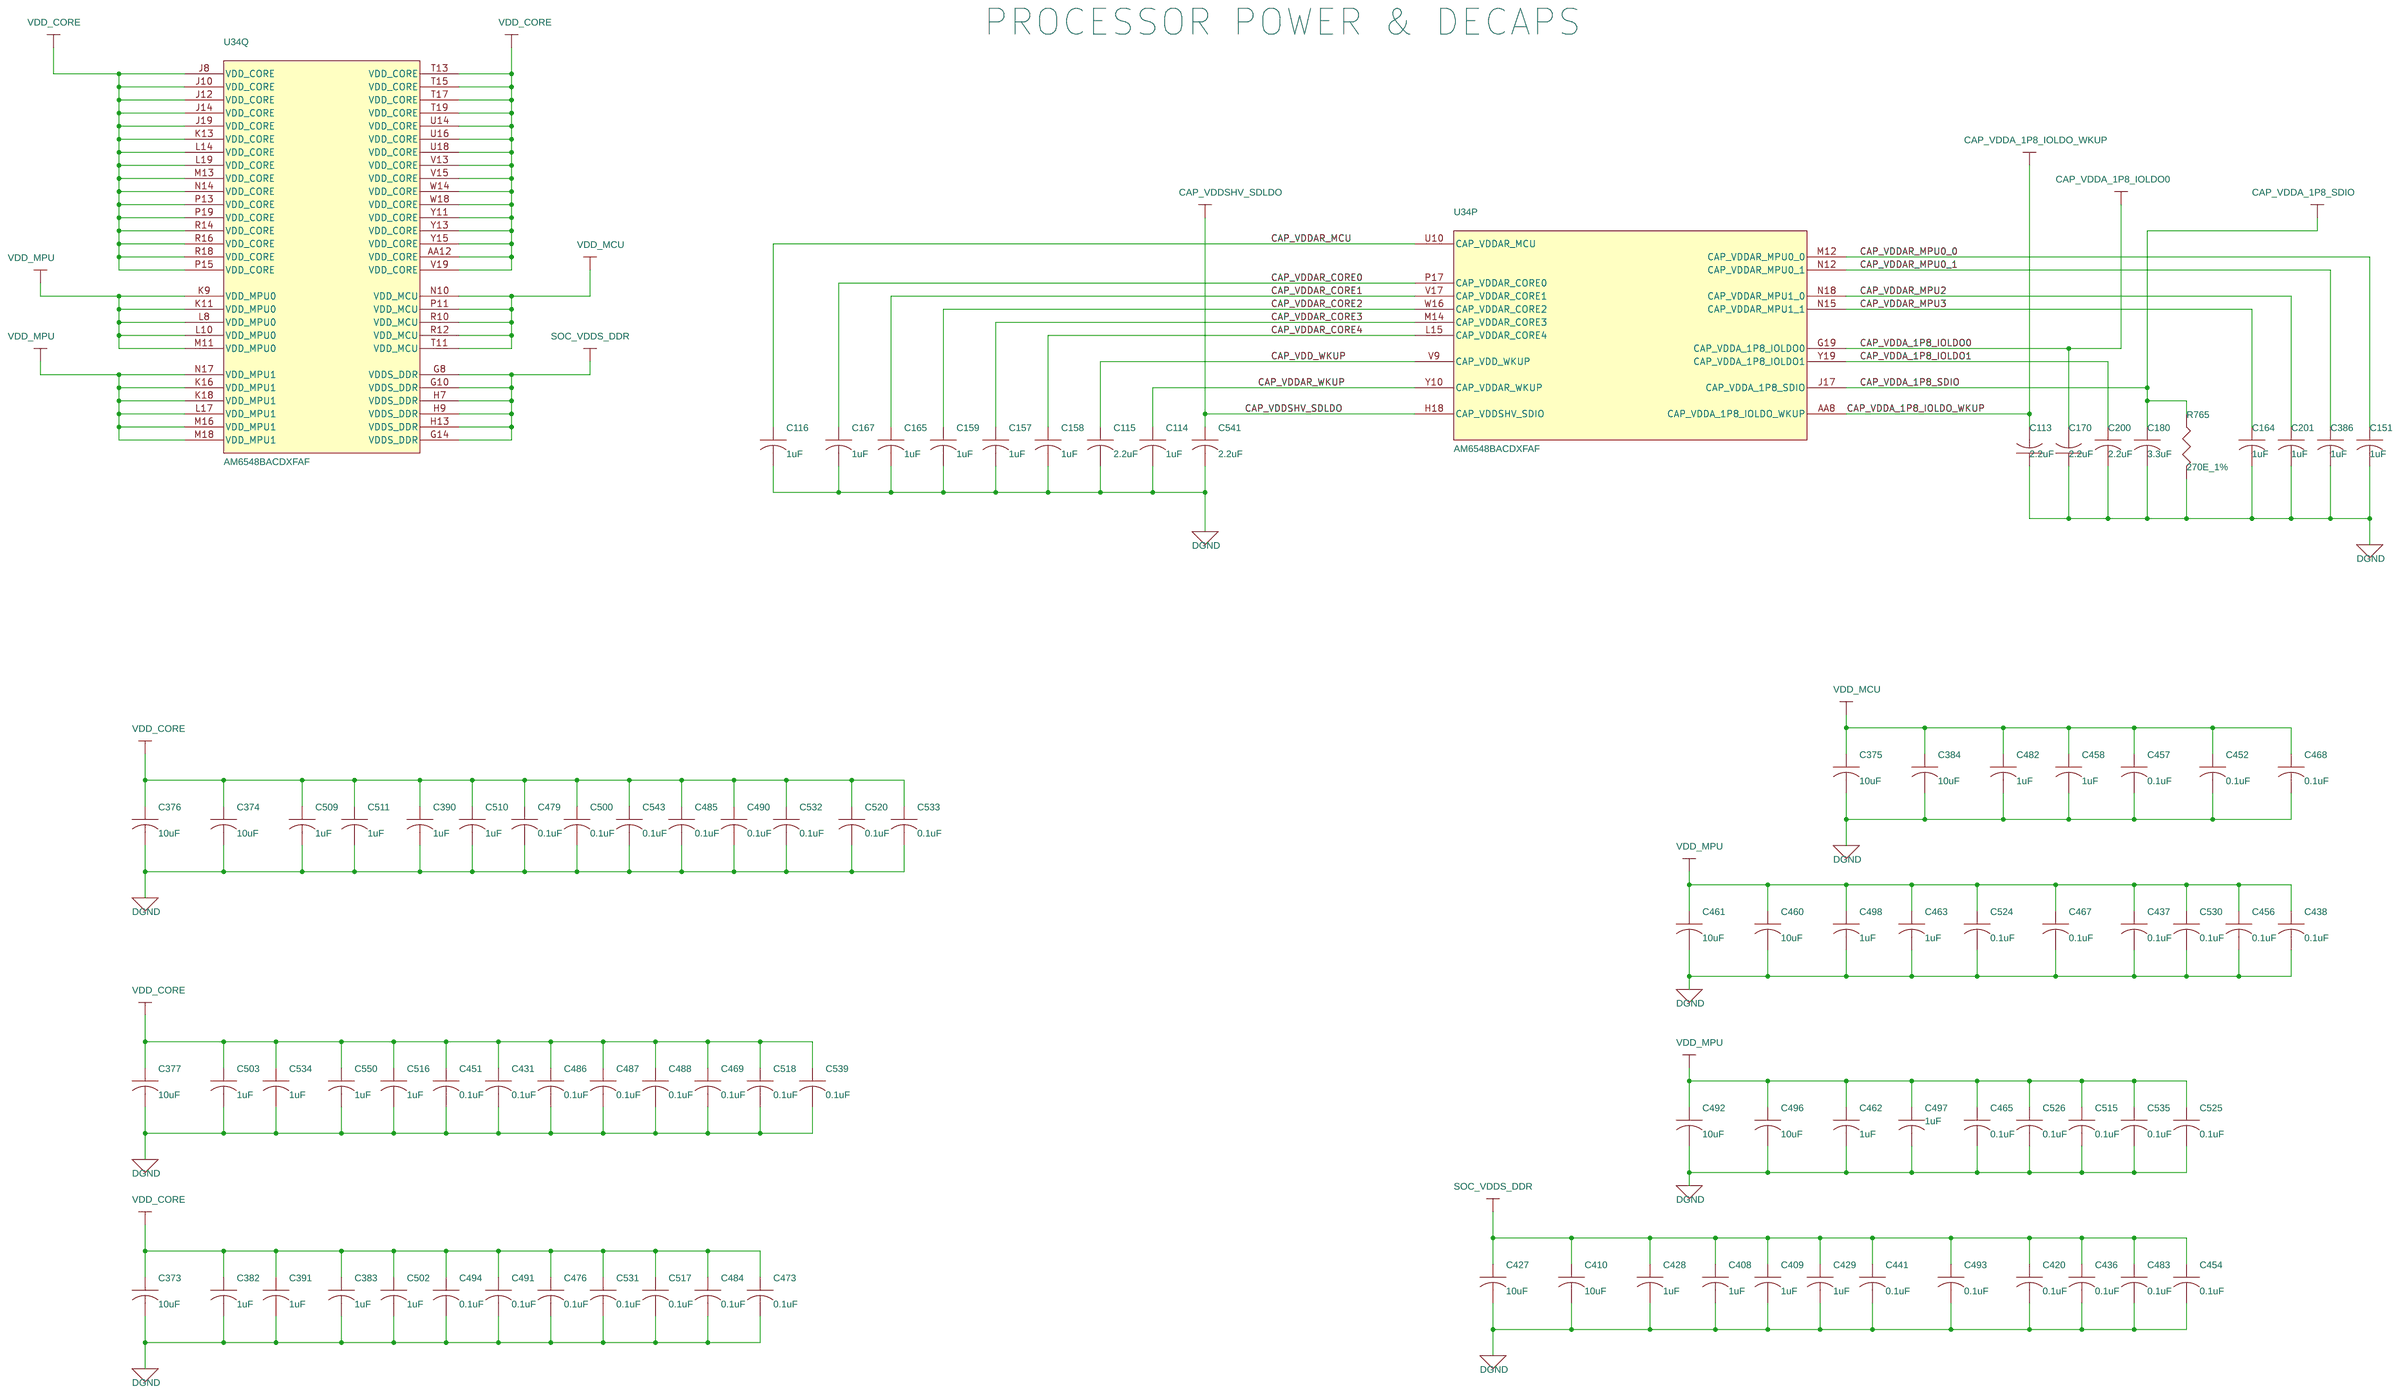
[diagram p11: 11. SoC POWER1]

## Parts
sheet 10. SoC CLOCK & RESET
B1  796136-1  [BATTH2_796136_1080X750_SMD_6-9]
C237  0.1uF  [CAP0201_0-5]
C238  0.1uF  [CAP0201_0-5]
C240  0.1uF  [CAP0201_0-5]
C241  0.1uF  [CAP0201_0-5]
C242  0.1uF  [CAP0201_0-5]
C401  18pF  [CAP0402_0-75]
C412  18pF  [CAP0402_0-75]
C584  18pF  [CAP0402_0-75]
C587  18pF  [CAP0402_0-75]
C600  18pF  [CAP0402_0-75]
C602  18pF  [CAP0402_0-75]
C603  0.1uF  [CAP0201_0-5]
C637  0.1uF  [CAP0201_0-5]
D10  TPD1E10B06DPY  [DIO_DFN0402]
D12  TPD1E10B06DPY  [DIO_DFN0402]
D13  TPD1E10B06DPY  [DIO_DFN0402]
Q18  IRLML6401  [TO_SOT23-123]
Q19  IRLML6401  [TO_SOT23-123]
Q20  IRLML6401  [TO_SOT23-123]
R309  10K  [RES0402_0-5]
R318  10K  [RES0402_0-5]
R320  10K  [RES0402_0-5]
R321  10K  [RES0402_0-5]
R448  0E  [RES0402_0-5]
R450  0E  [RES0402_0-5]
R455  1M_1%  [RES0402]
R457  0E  [RES0402_0-5]
R507  0E  [RES0402_0-5]
R510  1M_1%  [RES0402]
R511  0E  [RES0402_0-5]
R550  0E  [RES0402_0-5]
R551  0E  [RES0402_0-5]
R552  10K  [RES0402_0-5]
R563  1M_1%  [RES0402]
R564  0E  [RES0402_0-5]
R647  10K  [RES0402_0-5]
SW5  SKHMQLE010  [SW4_SKHMQLE010_240X260_SMD_3-1]
SW6  SKHMQLE010  [SW4_SKHMQLE010_240X260_SMD_3-1]
SW7  SKHMQLE010  [SW4_SKHMQLE010_240X260_SMD_3-1]
U52  SN74LVC3G17DCUR  [VSSOP8_19-68_85X95_0-9]
U91  MCP79410-I/SN  [SOIC8_1-8]
U125  TXS0102DCUR  [VSSOP8_19-68_85X95_0-9]
Y3  25.000MHz  [XTAL4_TXC_130X100_SMD_0-8]
Y4  24.576MHz  [XTAL4_TXC_130X100_SMD_0-8]
Y5  32.768KHz  [XTAL_ABS07_130X60_SMD_0-9]
sheet 11. SoC POWER1
C113  2.2uF  [CAP0603]
C114  1uF  [CAP0402_0-75]
C115  2.2uF  [CAP0402_0-75]
C116  1uF  [CAP0402_0-75]
C151  1uF  [CAP0402_0-75]
C157  1uF  [CAP0402_0-75]
C158  1uF  [CAP0402_0-75]
C159  1uF  [CAP0402_0-75]
C164  1uF  [CAP0402_0-75]
C165  1uF  [CAP0402_0-75]
C167  1uF  [CAP0402_0-75]
C170  2.2uF  [CAP0603]
C180  3.3uF  [CAP0402_0-75]
C200  2.2uF  [CAP0402_0-75]
C201  1uF  [CAP0402_0-75]
C373  10uF  [CAP0603_1]
C374  10uF  [CAP0603_1]
C375  10uF  [CAP0603_1]
C376  10uF  [CAP0603_1]
C377  10uF  [CAP0603_1]
C382  1uF  [CAP0402_0-75]
C383  1uF  [CAP0402_0-75]
C384  10uF  [CAP0603_1]
C386  1uF  [CAP0402_0-75]
C390  1uF  [CAP0402_0-75]
C391  1uF  [CAP0402_0-75]
C408  1uF  [CAP0402_0-75]
C409  1uF  [CAP0402_0-75]
C410  10uF  [CAP0603_1]
C420  0.1uF  [CAP0201_0-5]
C427  10uF  [CAP0603_1]
C428  1uF  [CAP0402_0-75]
C429  1uF  [CAP0402_0-75]
C431  0.1uF  [CAP0201_0-5]
C436  0.1uF  [CAP0201_0-5]
C437  0.1uF  [CAP0201_0-5]
C438  0.1uF  [CAP0201_0-5]
C441  0.1uF  [CAP0201_0-5]
C451  0.1uF  [CAP0201_0-5]
C452  0.1uF  [CAP0201_0-5]
C454  0.1uF  [CAP0201_0-5]
C456  0.1uF  [CAP0201_0-5]
C457  0.1uF  [CAP0201_0-5]
C458  1uF  [CAP0402_0-75]
C460  10uF  [CAP0603_1]
C461  10uF  [CAP0603_1]
C462  1uF  [CAP0402_0-75]
C463  1uF  [CAP0402_0-75]
C465  0.1uF  [CAP0201_0-5]
C467  0.1uF  [CAP0201_0-5]
C468  0.1uF  [CAP0201_0-5]
C469  0.1uF  [CAP0201_0-5]
C473  0.1uF  [CAP0201_0-5]
C476  0.1uF  [CAP0201_0-5]
C479  0.1uF  [CAP0201_0-5]
C482  1uF  [CAP0402_0-75]
C483  0.1uF  [CAP0201_0-5]
C484  0.1uF  [CAP0201_0-5]
C485  0.1uF  [CAP0201_0-5]
C486  0.1uF  [CAP0201_0-5]
C487  0.1uF  [CAP0201_0-5]
C488  0.1uF  [CAP0201_0-5]
C490  0.1uF  [CAP0201_0-5]
C491  0.1uF  [CAP0201_0-5]
C492  10uF  [CAP0603_1]
C493  0.1uF  [CAP0201_0-5]
C494  0.1uF  [CAP0201_0-5]
C496  10uF  [CAP0603_1]
C497  1uF  [CAP0402_0-75]
C498  1uF  [CAP0402_0-75]
C500  0.1uF  [CAP0201_0-5]
C502  1uF  [CAP0402_0-75]
C503  1uF  [CAP0402_0-75]
C509  1uF  [CAP0402_0-75]
C510  1uF  [CAP0402_0-75]
C511  1uF  [CAP0402_0-75]
C515  0.1uF  [CAP0201_0-5]
C516  1uF  [CAP0402_0-75]
C517  0.1uF  [CAP0201_0-5]
C518  0.1uF  [CAP0201_0-5]
C520  0.1uF  [CAP0201_0-5]
C524  0.1uF  [CAP0201_0-5]
C525  0.1uF  [CAP0201_0-5]
C526  0.1uF  [CAP0201_0-5]
C530  0.1uF  [CAP0201_0-5]
C531  0.1uF  [CAP0201_0-5]
C532  0.1uF  [CAP0201_0-5]
C533  0.1uF  [CAP0201_0-5]
C534  1uF  [CAP0402_0-75]
C535  0.1uF  [CAP0201_0-5]
C539  0.1uF  [CAP0201_0-5]
C541  2.2uF  [CAP0402_0-75]
C543  0.1uF  [CAP0201_0-5]
C550  1uF  [CAP0402_0-75]
R765  270E_1%  [RES0402_0-5]
sheet 16. DDR4 ECC & TERMINATIONS
U34  AM6548BACDXFAF  [BGA784_31-49_910X910_1-7]  (sections A,B,C,D,E,F,G,H,I,J,K,L,M,N,O,P,Q,R,S)
sheet 44. HARDWARE SCHEMATICS
ACC1  SPC02SYAN  [NA]
ACC2  SPC02SYAN  [NA]
ACC3  SPC02SYAN  [NA]
ACC4  MNT-103-BK-G  [NA]
ACC5  C17117  [BGASKT784_C17117_2170X2170_37-4]
ACC6  MAXWELL M4  [BGA784_31-49_910X910_1-7]
ACC7  SPC02SYAN  [NA]
ACC8  SPC02SYAN  [NA]
ACC9  ATS-54310R-C1-R0  [NA]
FID1  FID_40X80  [FID_40X80]
FID2  FID_40X80  [FID_40X80]
FID3  FID_40X80  [FID_40X80]
FID4  FID_40X80  [FID_40X80]
FID5  FID_40X80  [FID_40X80]
FID6  FID_40X80  [FID_40X80]
LBL1  THT-103-423-10  [NA]
LBL2  THT-103-423-10  [NA]
LBL3  THT-103-423-10  [NA]
Logo1  Texas Intruments  [TI_Stacked_Overlay_Small]
Logo2  For Evaluation only; not FCC approved for resale  [FCC_disclaimer]
Logo3  WEEE Mark  [TI_Stacked_Overlay_Small]
Logo4  CE Mark  [TI_Stacked_Overlay_Small]
M1  728  [NA]
M2  728  [NA]
M3  728  [NA]
M4  728  [NA]
M5  728  [NA]
M6  728  [NA]
M7  728  [NA]
M8  728  [NA]
M9  728  [NA]
M10  PLAIN WASHER_M3  [NA]
M11  PLAIN WASHER_M3  [NA]
M12  PLAIN WASHER_M3  [NA]
M13  PLAIN WASHER_M3  [NA]
M14  PLAIN WASHER_M3  [NA]
M15  PLAIN WASHER_M3  [NA]
M16  PLAIN WASHER_M3  [NA]
M17  PLAIN WASHER_M3  [NA]
M18  PLAIN WASHER_M3  [NA]
M19  PLAIN WASHER_M3  [NA]
MH1  HEX SPACER_M2.5 X 30  [NA]
MH2  HEX SPACER_M2.5 X 30  [NA]
MH3  HEX SPACER_M2.5 X 30  [NA]
MH4  HEX SPACER_M2.5 X 30  [NA]
MH5  HEX SPACER_M2.5 X 30  [NA]
MH6  HEX SPACER_M2.5 X 30  [NA]
MH7  HEX SPACER_M2.5 X 30  [NA]
MH8  HEX SPACER_M2.5 X 6  [NA]
MH9  HEX SPACER_M2.5 X 6  [NA]
MH10  HEX SPACER_M2.5 X 6  [NA]
MH11  HEX SPACER_M2.5 X 6  [NA]
MH12  HEX SPACER_M2.5 X 6  [NA]
MH13  PAN HEAD_M2.5 X 4  [NA]
MH14  PAN HEAD_M2.5 X 4  [NA]
MH15  PAN HEAD_M2.5 X 4  [NA]
MH16  PAN HEAD_M2.5 X 4  [NA]
MH17  PAN HEAD_M2.5 X 4  [NA]
MH18  PAN HEAD_M2.5 X 4  [NA]
MH19  PAN HEAD_M2.5 X 12  [NA]
MH20  PAN HEAD_M2.5 X 12  [NA]
MH21  PAN HEAD_M2.5 X 12  [NA]
MH22  PAN HEAD_M2.5 X 12  [NA]
MH23  PAN HEAD_M2.5 X 12  [NA]
MH24  PAN HEAD_M2.5 X 12  [NA]
MH25  PAN HEAD_M2.5 X 12  [NA]
MH26  PAN HEAD_M2.5 X 12  [NA]
MH27  PAN HEAD_M2.5 X 12  [NA]
MH28  HEX SPACER_M2.5 X 5  [NA]
MH29  HEX SPACER_M2.5 X 5  [NA]
MH30  HEX SPACER_M2.5 X 5  [NA]
MH31  HEX SPACER_M2.5 X 5  [NA]
MH32  HEX SPACER_M2.5 X 30  [NA]
MH33  HEX SPACER_M2.5 X 30  [NA]
MH34  PAN HEAD_M2.5 X 4  [NA]
MH35  PAN HEAD_M2.5 X 4  [NA]
MH36  PAN HEAD_M2.5 X 4  [NA]
MH37  PAN HEAD_M2.5 X 4  [NA]
PCB1  AM65x EVM BARE PCB  [NA]
PCBA1  AM6x IDK APPLICATION CARD  [NA]
PCBA2  AM6x USB3/PCIE SERDES CARD  [NA]
PCBA3  AM6x PCIE-2 LANE SERDES CARD  [NA]

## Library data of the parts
B1 = BATTERY: BATTERY HOLDER COIN CELL TOP LOAD SMD; Chkd/date: MANIRAJA/161017; Crtd /date: BAVISH/090211; Distributor_name: DIGIKEY; Distributor_part_number: A99327CT-ND; Height: 6.85MM; Mfr_name: AMP INCORPORATED; Mistral Part No: 130011020020-R; Package: SMD; Part_type: BATTERY HOLDER; Project: OMAPL1_PEC20; RoHS: RoHS; Temperature: NA; Tolerance: NA; Voltage: NA; Wattage: NA; Weight: NA; Datasheet: Y:\MIS_DATABASE\DATASHEETS\MISC\BATTERY\796136-1.PDF
C237 C238 C240-C242 C420 C431 C436-C438 C441 C451 C452 C454 C456 C457 C465 C467-C469 C473 C476 C479 C483-C488 C490 C491 C493 C494 C500 C515 C517 C518 C520 C524-C526 C530-C533 C535 C539 C543 C603 C637 = CAP: CAP CERAMIC 0.1uF 16V 10% X5R 0201; Chkd/date: MANIRAJA/120218; Crtd /date: MANIRAJA/120218; Custom_Duty: 15%; Customs_HS_Code: 85322990; Distributor_name: DIGIKEY; Distributor_part_number: 490-16742-1-ND; Height: 0.33MM; Mfr_name: MURATA; Mfr_part_number: GRM033R61C104KE84J; Mistral Part No: 120009030072-R; Package: 0201; Part_type: CAPACITORS\CERAMIC; Project: TI_MAXIE_CPB; RoHS: RoHS; Temperature: -55°C+85°C; Tolerance: 10%; Voltage: 16V; Wattage: NA; Weight: 0.33mg; Datasheet: Y:\MIS_DATABASE\DATASHEETS\CAPACITORS\GRM033R61C104KE84.PDF
C401 C412 C584 C587 C600 C602 = CAP: CAP CERAMIC 18pF 50V 5% C0G(NP0) 0402; Chkd/date: MANIRAJA/070220; Crtd /date: ALVY/070220; Custom_Duty: 15%; Customs_HS_Code: 85322990; Distributor_name: DIGIKEY; Distributor_part_number: 399-8952-1-ND; Footprint Path: Y:\MIS_DATABASE\Library\ALTIUM_TOOL\PCB_FOOTPRINTS\Altium_Footprint_Lib.PcbLib; Height: 0.55MM; Library Path: Y:\MIS_DATABASE\Library\ALTIUM_TOOL\SCHEMATICS_PARTS\MS_DISCRETE_Library.schlib; Mfr_name: KEMET; Mfr_part_number: C0402C180J5GAC7867; Mistral Part No: 120011090034-R; Package: 0402; Part_type: CAPACITORS\CERAMIC; Project: TI_MAXIE_CPB; RoHS: RoHS; Temperature: -55°C+125°C; Tolerance: 5%; Voltage: 50V; Wattage: NA; Weight: 0.65mg; Datasheet: Y:\MIS_DATABASE\DATASHEETS\CAPACITORS\KEMET-C0G_SERIES.PDF
D10 D12 D13 = DIODE_PESD: DIODE 1CH ESD PROTECTION SMD(0402); Chkd/date: USMAN/021214; Crtd /date: VASANTHA/181114; Custom_Duty: 15%; Customs_HS_Code: 85423100; Distributor_name: DIGIKEY; Distributor_part_number: 296-30406-1-ND; Height: 0.45MM; Mfr_name: TEXAS INSTRUMENTS; Mistral Part No: 130014110022-R; Package: SMD; Part_type: DIODE\MISC; Project: GALILEO_EVM; RoHS: RoHS; Temperature: -40°C+125°C; Tolerance: NA; Voltage: NA; Wattage: NA; Weight: NA; Datasheet: Y:\MIS_DATABASE\DATASHEETS\ICS\INTERFACE\TPD1E10B06.PDF
Q18-Q20 = MOSFET_IRLML6401TR: TRANSISTOR MOSFET P-CHANNEL SOT23-3; Chkd/date: SHREESHAIL/020206; Crtd /date: MAZHAR/040505; Custom_Duty: 15%; Customs_HS_Code: 85412900; Distributor_name: DIGIKEY; Distributor_part_number: IRLML6401PBFCT-ND; Height: 1.11MM; Mfr_name: IRF; Mfr_part_number: IRLML6401TRPBF; Mistral Part No: 130009031213-P; Package: SOT23-3; Part_type: TRANSISTOR\MOSFET; Project: G4_SVGA; Remarks: Part# replaced from “IRLML6401TR” to “IRLML6401TRPBF” making as a Pb-free part. (BAVISH/220311).; RoHS: Pb-Free; Temperature: -55°C+150°C; Tolerance: NA; Voltage: NA; Wattage: NA; Weight: NA; Datasheet: Y:\MIS_DATABASE\DATASHEETS\DISCRETES\TRANSISTORS_FETS\IRLML6401.PDF
R309 R318 R320 R321 R552 R647 = RESISTOR: RES 10K 1/16W 5% 0402; Chkd/date: VASANTHA/061216; Crtd /date: MAZHAR/230805; Custom_Duty: 15%; Customs_HS_Code: 85332119; Distributor_name: DIGIKEY; Distributor_part_number: 311-10KJRCT-ND; Footprint Path: Y:\MIS_DATABASE\Library\ALTIUM_TOOL\PCB_FOOTPRINTS\Altium_Footprint_Lib.PcbLib; Height: 0.40MM; Library Path: Y:\MIS_DATABASE\Library\ALTIUM_TOOL\SCHEMATICS_PARTS\MS_DISCRETE_Library.schlib; Mfr_name: YAGEO AMERICA; Mfr_part_number: RC0402JR-0710KL; Mistral Part No: 110009030208-R; Package: 0402; Part_type: RESISTORS\FIXED; Project: HSE; RoHS: Pb-Free; Temperature: -55°C+155°C; Tolerance: 5%; Voltage: NA; Wattage: 1/16W; Weight: 0.65mg; Datasheet: Y:\MIS_DATABASE\DATASHEETS\RESISTORS\YAGEO-RC0402.PDF
R448 R450 R457 R507 R511 R550 R551 R564 = RESISTOR: RES 0E 1/16W 0402; Chkd/date: VASANTHA/201216; Crtd /date: MUDDU/190810; Custom_Duty: 15%; Customs_HS_Code: 85332119; Distributor_name: DIGIKEY; Distributor_part_number: 541-0.0JCT-ND; Footprint Path: Y:\MIS_DATABASE\Library\ALTIUM_TOOL\PCB_FOOTPRINTS\Altium_Footprint_Lib.PcbLib; Height: 0.40MM; Library Path: Y:\MIS_DATABASE\Library\ALTIUM_TOOL\SCHEMATICS_PARTS\MS_DISCRETE_Library.schlib; Mfr_name: VISHAY; Mfr_part_number: CRCW04020000Z0ED; Mistral Part No: 110010080019-P; Package: 0402; Part_type: RESISTORS\FIXED; Project: PB_BUGBASE; RoHS: Pb-Free; Temperature: -55°C+155°C; Tolerance: NA; Voltage: NA; Wattage: 1/16W; Weight: 0.65g/1000pcs; Datasheet: Y:\MIS_DATABASE\DATASHEETS\RESISTORS\CRCW0603.PDF
R455 R510 R563 = RESISTOR: RES 1M 1/16W 1% 0402; Chkd/date: VASANTHA/200614; Crtd /date: NAVEED/170614; Custom_Duty: 15%; Customs_HS_Code: 85332119; Distributor_name: DIGIKEY; Distributor_part_number: RMCF0402FT1M00CT-ND; Footprint Path: Y:\MIS_DATABASE\Library\ALTIUM_TOOL\PCB_FOOTPRINTS\Altium_Footprint_Lib.PcbLib; Height: 0.40MM; Library Path: Y:\MIS_DATABASE\Library\ALTIUM_TOOL\SCHEMATICS_PARTS\MS_DISCRETE_Library.schlib; Mfr_name: STACKPOLE ELECTRONICS; Mfr_part_number: RMCF0402FT1M00; Mistral Part No: 110014060045-R; Package: 0402; Part_type: RESISTORS\FIXED; Project: AEGIS_POM; RoHS: RoHS; Temperature: -55°C+155°C; Tolerance: 1%; Voltage: NA; Wattage: 1/16W; Weight: 0.57mg; Datasheet: Y:\MIS_DATABASE\DATASHEETS\RESISTORS\RMCF-SERIES1.PDF
SW5-SW7 = SW4_SKHUPLE010: SWITCH TACTILE SPST ST SMD; Chkd/date: MANIRAJA/051017; Crtd /date: MANIRAJA/051017; Custom_Duty: 24%; Customs_HS_Code: 85369090; Distributor_name: MOUSER; Distributor_part_number: 688-SKHMQLE010; Height: 3.10MM; Mfr_name: ALPS; Mistral Part No: 130017100007-R; Package: SMD; Part_type: ELECTRO-MECHANICAL\SWITCH; Project: TI_MAXIE_CPB; RoHS: RoHS; Temperature: -30°C+85°C; Tolerance: NA; Voltage: NA; Wattage: NA; Weight: NA; Datasheet: Y:\MIS_DATABASE\DATASHEETS\MISC\SWITCHES\SKHMQLE010.PDF
U52 = SN74LVC3G17DCUR_VSSOP8: IC TRIPLE SCHMITT-TRIGGER BUFFER VSSOP8; Chkd/date: MANIRAJA/280917; Crtd /date: MANIRAJA/280917; Custom_Duty: 15%; Customs_HS_Code: 85423100; Distributor_name: DIGIKEY; Distributor_part_number: 296-18818-1-ND; Height: 0.90MM; Mfr_name: TEXAS INSTRUMENTS; Mistral Part No: 141017090019-R; Package: VSSOP8; Part_type: ICS\DIGITAL\COMBINATIONAL; Project: TI_MAXIE_CPB; RoHS: RoHS; Temperature: -40°C+125°C; Tolerance: NA; Voltage: NA; Wattage: NA; Weight: 9.6mg; Datasheet: Y:\MIS_DATABASE\DATASHEETS\ICS\DIGITAL\COMBINATIONAL\SN74LVC3G17.PDF
U91 = MCP79410_SOIC8: IC BATTERY-BACKED I2C RTCC WITH SRAM,EEPROM SOIC8; Chkd/date: MANIRAJA/190617; Crtd /date: MANIRAJA/190617; Custom_Duty: 15%; Customs_HS_Code: 85423100; Distributor_name: DIGIKEY; Distributor_part_number: MCP79410-I/SN-ND; Height: 1.75MM; Mfr_name: MICROCHIP; Mistral Part No: 142017060006-R; Package: SOIC8; Part_type: ICS\POWER\BATTERY MANGEMENT; Project: TI_SVB_CONTROLLER CARD; RoHS: RoHS; Temperature: -40°C+85°C; Tolerance: NA; Voltage: NA; Wattage: NA; Weight: 540mg; Datasheet: Y:\MIS_DATABASE\DATASHEETS\ICS\POWER\MCP7941XX.PDF
U125 = TXS0102DCUR_VSSOP8: IC 2BIT BI-DIR VOLTAGE-LEVEL TRANSLATOR US8(VSSOP8); Chkd/date: MANIRAJA/130617; Crtd /date: SHREESHAIL/190108; Custom_Duty: 15%; Customs_HS_Code: 85423100; Distributor_name: DIGIKEY; Distributor_part_number: 296-21931-1-ND; Footprint Path: Y:\MIS_DATABASE\Library\ALTIUM_TOOL\PCB_FOOTPRINTS\Altium_Footprint_Lib.PcbLib; Height: 0.90MM; Library Path: Y:\MIS_DATABASE\Library\ALTIUM_TOOL\SCHEMATICS_PARTS\MS_MISCINTERFACE_Library.schlib; Mfr_name: TEXAS INSTRUMENTS; Mistral Part No: 141009030376-R; Package: US8; Part_type: ICS\INTERFACE\LEVEL TRANSLATOR; Project: SD_WATERLOO; RoHS: RoHS; Temperature: -40°C+85°C; Tolerance: NA; Voltage: NA; Wattage: NA; Weight: 9.6mg; Datasheet: Y:\MIS_DATABASE\DATASHEETS\ICS\INTERFACE\TXS0102.PDF
Y3 = CRY4_13: CRY 25.000MHz 10pF SMD; Chkd/date: MANIRAJA/060619; Crtd /date: ALVY/060619; Custom_Duty: 24%; Customs_HS_Code: 85439000; Distributor_name: DIGIKEY; Distributor_part_number: 887-1326-1-ND; Footprint Path: Y:\MIS_DATABASE\Library\ALTIUM_TOOL\PCB_FOOTPRINTS\Altium_Footprint_Lib.PcbLib; Height: 0.80MM; Library Path: Y:\MIS_DATABASE\Library\ALTIUM_TOOL\SCHEMATICS_PARTS\MS_DISCRETE_Library.schlib; Mfr_name: TXC CORPORATION; Mfr_part_number: 7M-25.000MEEQ-T; Mistral Part No: 130019060005-R; Package: SMD; Part_type: CRYSTAL; Project: TI_MAXIE_CPB; RoHS: RoHS; Temperature: -20°C+70°C; Tolerance: NA; Voltage: NA; Wattage: NA; Weight: 16mg; Datasheet: Y:\MIS_DATABASE\DATASHEETS\MISC\CRY_OSC\7M-SER.PDF
Y4 = CRY4_13: CRY 24.576MHz 18pF SMD; Chkd/date: MANIRAJA/240118; Crtd /date: MANIRAJA/240118; Custom_Duty: 24%; Customs_HS_Code: 85439000; Distributor_name: DIGIKEY; Distributor_part_number: 887-2373-1-ND; Height: 0.80MM; Mfr_name: TXC CORPORATION; Mfr_part_number: 7M-24.576MAAJ-T; Mistral Part No: 130018010021-R; Package: SMD; Part_type: CRYSTAL; Project: TI_MAXIE_CPB; RoHS: RoHS; Temperature: -20°C+70°C; Tolerance: NA; Voltage: NA; Wattage: NA; Weight: 16mg; Datasheet: Y:\MIS_DATABASE\DATASHEETS\MISC\CRY_OSC\7M-SER.PDF
Y5 = CRY: CRY 32.768KHz 12.5pF SMD; Chkd/date: VASANTHA/050117; Crtd /date: MAZHAR/250907; Custom_Duty: 24%; Customs_HS_Code: 85439000; Distributor_name: DIGIKEY; Distributor_part_number: 535-9542-1-ND; Height: 0.90MM; Mfr_name: ABRACON; Mfr_part_number: ABS07-32.768KHZ-T; Mistral Part No: 130009030082-R; Package: SMD; Part_type: CRYSTAL; Project: SMART VIEW_IP CAMERA; RoHS: RoHS; Temperature: -40°C+85°C; Tolerance: NA; Voltage: NA; Wattage: NA; Weight: 16mg; Datasheet: Y:\MIS_DATABASE\DATASHEETS\MISC\CRY_OSC\ABS07.PDF
C113 C170 = CAP: CAP CERAMIC 2.2uF 10V 10% X5R 0603; Alternate_mfr_name_C: PANASONIC-ECG; Alternate_mfr_part_number_C: ECJ-1VB1A225K; Chkd/date: SHREESHAIL/280507; Crtd /date: MAZHAR/291106; Custom_Duty: 15%; Customs_HS_Code: 85322990; Distributor_name: MOUSER; Distributor_name_C: DIGIKEY; Distributor_part_number: 80-C0603C225K8P; Distributor_part_number_C: PCC2397CT-ND; Height: 0.90MM; Mfr_name: KEMET; Mfr_part_number: C0603C225K8PACTU; Mistral Part No: 120009030289-R; Package: 0603; Part_type: CAPACITORS\CERAMIC; Project: PMP LCD BOARD; RoHS: RoHS; Tolerance: 10%; Voltage: 10V; Datasheet: Y:\MIS_DATABASE\DATASHEETS\CAPACITORS\KEMET-C08.PDF
C114 C116 C151 C157-C159 C164 C165 C167 C201 C382 C383 C386 C390 C391 C408 C409 C428 C429 C458 C462 C463 C482 C497 C498 C502 C503 C509-C511 C516 C534 C550 = CAP: CAP CERAMIC 1uF 16V 20% X5R 0402; Chkd/date: MANIRAJA/150218; Crtd /date: ALVY/150218; Custom_Duty: 15%; Customs_HS_Code: 85322990; Distributor_name: DIGIKEY; Distributor_part_number: 587-5514-1-ND; Footprint Path: Y:\MIS_DATABASE\Library\ALTIUM_TOOL\PCB_FOOTPRINTS\Altium_Footprint_Lib.PcbLib; Height: 0.55MM; Library Path: Y:\MIS_DATABASE\Library\ALTIUM_TOOL\SCHEMATICS_PARTS\MS_DISCRETE_Library.schlib; Mfr_name: TAIYO YUDEN; Mfr_part_number: EMK105BJ105MV-F; Mistral Part No: 120018020006-R; Package: 0402; Part_type: CAPACITORS\CERAMIC; Project: TI_MAXIE_CPB; RoHS: RoHS; Temperature: -55°C+85°C; Tolerance: 20%; Voltage: 16V; Wattage: NA; Weight: 0.65mg; Datasheet: Y:\MIS_DATABASE\DATASHEETS\CAPACITORS\EMK105BJ105MV-F.PDF
C115 C200 C541 = CAP: CAP CERAMIC 2.2uF 10V 20% X5R 0402; Chkd/date: MANIRAJA/240118; Crtd /date: MANIRAJA/240118; Custom_Duty: 15%; Customs_HS_Code: 85322990; Distributor_name: DIGIKEY; Distributor_part_number: 490-12254-1-ND; Height: 0.55MM; Mfr_name: MURATA; Mfr_part_number: GRT155R61A225ME01D; Mistral Part No: 120018010016-R; Package: 0402; Part_type: CAPACITORS\CERAMIC; Project: TI_MAXIE_CPB; RoHS: RoHS; Temperature: -55°C+85°C; Tolerance: 20%; Voltage: 10V; Wattage: NA; Weight: 0.65mg; Datasheet: Y:\MIS_DATABASE\DATASHEETS\CAPACITORS\GRT155R61A225ME01.PDF
C180 = CAP: CAP CERAMIC 3.3uF 6.3V 20% X5R 0402; Chkd/date: NAVEED/270315; Crtd /date: VASANTHA/130215; Custom_Duty: 15%; Customs_HS_Code: 85322990; Distributor_name: DIGIKEY; Distributor_part_number: 445-7394-1-ND; Footprint Path: Y:\MIS_DATABASE\Library\ALTIUM_TOOL\PCB_FOOTPRINTS\Altium_Footprint_Lib.PcbLib; Height: 0.60MM; Library Path: Y:\MIS_DATABASE\Library\ALTIUM_TOOL\SCHEMATICS_PARTS\MS_DISCRETE_Library.schlib; Mfr_name: TDK CORPORATION; Mfr_part_number: C1005X5R0J335M050BC; Mistral Part No: 120015020002-R; Package: 0402; Part_type: CAPACITORS\CERAMIC; Project: GALILEO_EVM; RoHS: RoHS; Temperature: -55°C+85°C; Tolerance: 20%; Voltage: 6.3V; Wattage: NA; Weight: 0.65mg; Datasheet: Y:\MIS_DATABASE\DATASHEETS\CAPACITORS\TDK-C-SER_JUL17.PDF
C373-C377 C384 C410 C427 C460 C461 C492 C496 = CAP: CAP CERAMIC 10uF 10V 10% X5R 0603; Chkd/date: MANIRAJA/230118; Crtd /date: MANIRAJA/230118; Custom_Duty: 15%; Customs_HS_Code: 85322990; Distributor_name: DIGIKEY; Distributor_part_number: 478-10766-1-ND; Height: 0.94MM; Mfr_name: AVX CORPORATION; Mfr_part_number: 0603ZD106KAT2A; Mistral Part No: 120010080001-R; Package: 0603; Part_type: CAPACITORS\CERAMIC; Project: TI_MAXIE_CPB; RoHS: RoHS; Temperature: -55°C+85°C; Tolerance: 10%; Voltage: 10V; Wattage: NA; Weight: 2mg; Datasheet: Y:\MIS_DATABASE\DATASHEETS\CAPACITORS\AVX_MLC.PDF
R765 = RESISTOR: RES 270E 1/16W 1% 0402; Chkd/date: USMAN/310812; Crtd /date: CHAITHANYA/300812; Custom_Duty: 15%; Customs_HS_Code: 85332119; Distributor_name: DIGIKEY; Distributor_part_number: 541-270LCT-ND; Footprint Path: Y:\MIS_DATABASE\Library\ALTIUM_TOOL\PCB_FOOTPRINTS\Altium_Footprint_Lib.PcbLib; Height: 0.40MM; Library Path: Y:\MIS_DATABASE\Library\ALTIUM_TOOL\SCHEMATICS_PARTS\MS_DISCRETE_Library.schlib; Mfr_name: VISHAY; Mfr_part_number: CRCW0402270RFKED; Mistral Part No: 110012080083-R; Package: 0402; Part_type: RESISTORS\FIXED; Project: ITS-CONTROLER_CARD; RoHS: RoHS; Temperature: -55°C+155°C; Tolerance: 1%; Voltage: NA; Wattage: 1/16W; Weight: 0.65mg; Datasheet: Y:\MIS_DATABASE\DATASHEETS\RESISTORS\CRCW0603.PDF
U34 = AM654X_BGA784: IC AM65X MICRO CONTROLLER UNIT BGA784; Chkd/date: ALVY/010721; Crtd /date: MANIRAJA/010721; Custom_Duty: 15%; Customs_HS_Code: 85423100; Distributor_name: NA; Distributor_part_number: NA; Footprint Path: Y:\MIS_DATABASE\Library\ALTIUM_TOOL\PCB_FOOTPRINTS\Altium_Footprint_Lib.PcbLib; Height: 1.63MM; Library Path: Y:\MIS_DATABASE\Library\ALTIUM_TOOL\SCHEMATICS_PARTS\MS_MICROCONTROLLER_Library.schlib; Mfr_name: TEXAS INSTRUMENTS; Mistral Part No: 141221070001; Package: BGA784; Part_type: ICS\DIGITAL\MICROCONTROLLER; Project: TI_AM65X_CP; RoHS: NA; Temperature: NA; Tolerance: NA; Voltage: NA; Wattage: NA; Weight: NA; Datasheet: Y:\MIS_DATABASE\DATASHEETS\ICS\DIGITAL\MICROCONTROLLER\MAXWELLM4.PDF
ACC1-ACC3 ACC7 ACC8 = ACCESSORY: ACCESSORIE JUMPER SHORTING GOLD FLASH; Chkd/date: SUHAS\211010; Crtd /date: USMAN/301208; Distributor_name: DIGIKEY; Distributor_part_number: S9001-ND; Footprint Path: Y:\MIS_DATABASE\Library\ALTIUM_TOOL\PCB_FOOTPRINTS\Altium_Footprint_Lib.PcbLib; Library Path: Y:\MIS_DATABASE\Library\ALTIUM_TOOL\SCHEMATICS_PARTS\MS_MECHANICAL_Library.schlib; Mfr_name: SULLINS CONNECTOR; Mistral Part No: 160009030153-R; Part_type: ACCESSORIES; Project: SMART VIEW_NVR; RoHS: RoHS; Temperature: -55°C+105°C; Datasheet: Y:\MIS_DATABASE\DATASHEETS\MISC\MODULES\SPC02SYAN.PDF
ACC4 = ACCESSORY: ACCESSORIE CONNECTOR SHUNT 2X3 POS EDGE MOUNT SOCKET STRIP; Chkd/date: MANIRAJA/141117; Crtd /date: MANIRAJA/141117; Distributor_name: DIGIKEY; Distributor_part_number: SAM10620-ND; Mfr_name: SAMTEC; Mistral Part No: 160017110050-R; Part_type: ACCESSORIES; Project: TI_MAXIE_CPB; RoHS: RoHS; Temperature: -55°C+125°C; Datasheet: Y:\MIS_DATABASE\DATASHEETS\MISC\ACCESSORIES\SAMTEC-MNT-SER.PDF
ACC5 = ACCESSORY: ACCESSORIE BGA SOCKET MAXWELL M4 MICROPROCESSOR BGA784; Chkd/date: MANIRAJA/190917; Crtd /date: MANIRAJA/190917; Distributor_name: NA; Distributor_part_number: NA; Height: 37.34MM; Mfr_name: IRONWOOD ELECTRONICS; Mistral Part No: 160017090045; Package: BGA784; Part_type: ACCESSORIES; Project: TI_SVB_MAXWELL_DUT; Temperature: NA; Tolerance: NA; Voltage: NA; Wattage: NA; Weight: 105.46g; Datasheet: Y:\MIS_DATABASE\DATASHEETS\MISC\ACCESSORIES\C17117.PDF
ACC6 = ACCESSORY: IC MAXWELL MICRO CONTROLLER UNIT BGA784; Chkd/date: MANIRAJA/130717; Crtd /date: MANIRAJA/130717; Custom_Duty: 15%; Customs_HS_Code: 85423100; Distributor_name: NA; Distributor_part_number: NA; Height: 1.63MM; Library Ref: MAXWELLM4; Mfr_name: TEXAS INSTRUMENTS; Mistral Part No: 141217070003; Package: BGA784; Part_type: ICS\DIGITAL\MICROCONTROLLER; Project: TI_SVB_MAXWELL_DUT; Temperature: NA; Tolerance: NA; Voltage: NA; Wattage: NA; Weight: NA; Datasheet: Y:\MIS_DATABASE\DATASHEETS\ICS\DIGITAL\MICROCONTROLLER\MAXWELLM4.PDF
ACC9 = ACCESSORY: ACCESSORIE BGA HEATSINK STRAIGHT FIN 31MM X 31MM X 19.5MM; Chkd/date: MANIRAJA/040718; Crtd /date: MANIRAJA/040718; Distributor_name: DIGIKEY; Distributor_part_number: ATS1238-ND; Mfr_name: ATS; Mistral Part No: 160018070031-R; Part_type: ACCESSORIES; Project: TI_MAXIE_CPB; RoHS: RoHS; Datasheet: Y:\MIS_DATABASE\DATASHEETS\MISC\ACCESSORIES\ATS-54310R-C1-R0.PDF
FID1-FID6 = Fiducial
LBL1-LBL3 = ACCESSORY_THT-3-423-10: ACCESSORIE 1 WORKHORSE POLYSTER LABLE 0.25" X 1"; Chkd/date: MANIRAJA/270218; Crtd /date: ALVY/260218; Footprint Path: Y:\MIS_DATABASE\Library\ALTIUM_TOOL\PCB_FOOTPRINTS\Altium_Footprint_Lib.PcbLib; Library Path: Y:\MIS_DATABASE\Library\ALTIUM_TOOL\SCHEMATICS_PARTS\MS_MECHANICAL_Library.schlib; Mfr_name: BRADY; Mistral Part No: 160018020185; Part_type: ACCESSORIES; Project: TI_MAXIE_CPB
Logo1 Logo3 Logo4 = TI_Logo
Logo2 = FCC_disclaimer
M1-M9 = ACCESSORY: ACCESSORIE RECESSED BUMPER 19.05MM DIA; Chkd/date: MANIRAJA/110718; Crtd /date: MANIRAJA/110718; Distributor_name: DIGIKEY; Distributor_part_number: 36-728-ND; Mfr_name: KEYSTONE; Mistral Part No: 160018070042-R; Part_type: ACCESSORIES; Project: TI_MAXIE_CPB; RoHS: RoHS; Weight: 2042mg; Datasheet: Y:\MIS_DATABASE\DATASHEETS\MISC\ACCESSORIES\728.PDF
M10-M19 = WASHER_PLAIN: PLAIN WASHER FOR M3 SS-316; Chkd/date: MANIRAJA/190218; Crtd /date: MANIRAJA/190218; Distributor_name: DIGIKEY; Distributor_part_number: 36-4692-ND; Footprint Path: Y:\MIS_DATABASE\Library\ALTIUM_TOOL\PCB_FOOTPRINTS\Altium_Footprint_Lib.PcbLib; Library Path: Y:\MIS_DATABASE\Library\ALTIUM_TOOL\SCHEMATICS_PARTS\MS_MECHANICAL_Library.schlib; Mfr_name: KEYSTONE; Mfr_part_number: 4692; Mistral Part No: 160018020078-R; Package: SS; Part_type: MECHANICAL\WASHERS; Project: TI_MAXIE_CPB; RoHS: RoHS; Datasheet: Y:\MIS_DATABASE\DATASHEETS\MISC\MECHANICAL\4692.PDF
MH1-MH7 = HEX_SPACER_FF: HEX SPACER FEMALE TO FEMALE M2.5 X 30MM; Chkd/date: MANIRAJA/190218; Crtd /date: MANIRAJA/190218; Distributor_name: DIGIKEY; Distributor_part_number: 732-10626-ND; Footprint Path: Y:\MIS_DATABASE\Library\ALTIUM_TOOL\PCB_FOOTPRINTS\Altium_Footprint_Lib.PcbLib; Height: 30.00MM; Library Path: Y:\MIS_DATABASE\Library\ALTIUM_TOOL\SCHEMATICS_PARTS\MS_MECHANICAL_Library.schlib; Mfr_name: WURTH ELECTRONICS; Mfr_part_number: 970300151; Mistral Part No: 160018020071-R; Package: SS; Part_type: MECHANICAL\SPACER; Project: TI_MAXIE_CPB; RoHS: RoHS; Datasheet: Y:\MIS_DATABASE\DATASHEETS\MISC\MECHANICAL\970XXX1.PDF
MH8-MH12 = HEX_SPACER_FF: HEX SPACER FEMALE TO FEMALE M2.5 X 6MM; Chkd/date: MANIRAJA/190218; Crtd /date: MANIRAJA/190218; Distributor_name: DIGIKEY; Distributor_part_number: 732-10524-ND; Footprint Path: Y:\MIS_DATABASE\Library\ALTIUM_TOOL\PCB_FOOTPRINTS\Altium_Footprint_Lib.PcbLib; Height: 6.00MM; Library Path: Y:\MIS_DATABASE\Library\ALTIUM_TOOL\SCHEMATICS_PARTS\MS_MECHANICAL_Library.schlib; Mfr_name: WURTH ELECTRONICS; Mfr_part_number: 970060151; Mistral Part No: 160018020075-R; Package: SS; Part_type: MECHANICAL\SPACER; Project: TI_MAXIE_CPB; RoHS: RoHS; Datasheet: Y:\MIS_DATABASE\DATASHEETS\MISC\MECHANICAL\970XXX1.PDF
MH13-MH18 MH34-MH37 = SCREW_PAN: PHILLIPS PAN HEAD SCREW - M2.5 X 4 SS-316; Chkd/date: MANIRAJA/190218; Crtd /date: MANIRAJA/190218; Distributor_name: DIGIKEY; Distributor_part_number: 36-29300-ND; Footprint Path: Y:\MIS_DATABASE\Library\ALTIUM_TOOL\PCB_FOOTPRINTS\Altium_Footprint_Lib.PcbLib; Height: 4.00MM; Library Path: Y:\MIS_DATABASE\Library\ALTIUM_TOOL\SCHEMATICS_PARTS\MS_MECHANICAL_Library.schlib; Mfr_name: KEYSTONE; Mfr_part_number: 29300; Mistral Part No: 160018020076-R; Package: SS; Part_type: MECHANICAL\SCREWS; Project: TI_MAXIE_CPB; RoHS: RoHS; Datasheet: Y:\MIS_DATABASE\DATASHEETS\MISC\MECHANICAL\29300.PDF
MH19-MH27 = SCREW_PAN: PHILLIPS PAN HEAD SCREW - M2.5 X 12; Chkd/date: MANIRAJA/110718; Crtd /date: MANIRAJA/110718; Distributor_name: DIGIKEY; Distributor_part_number: 36-29304-ND; Height: 12.00MM; Mfr_name: KEYSTONE; Mfr_part_number: 29304; Mistral Part No: 160018070043-R; Part_type: ACCESSORIES; Project: TI_MAXIE_CPB; RoHS: RoHS; Datasheet: Y:\MIS_DATABASE\DATASHEETS\MISC\MECHANICAL\29304.PDF
MH28-MH31 = HEX_SPACER_MF: HEX SPACER MALE TO FEMALE M2.5 X 5MM; Chkd/date: MANIRAJA/190218; Crtd /date: MANIRAJA/190218; Distributor_name: DIGIKEY; Distributor_part_number: 732-10380-ND; Footprint Path: Y:\MIS_DATABASE\Library\ALTIUM_TOOL\PCB_FOOTPRINTS\Altium_Footprint_Lib.PcbLib; Height: 5.00MM; Library Path: Y:\MIS_DATABASE\Library\ALTIUM_TOOL\SCHEMATICS_PARTS\MS_MECHANICAL_Library.schlib; Mfr_name: WURTH ELECTRONICS; Mfr_part_number: 971050151; Mistral Part No: 160018020072-R; Package: SS; Part_type: MECHANICAL\SPACER; Project: TI_MAXIE_CPB; RoHS: RoHS; Datasheet: Y:\MIS_DATABASE\DATASHEETS\MISC\MECHANICAL\971XX0XX1.PDF
MH32 MH33 = HEX_SPACER_MF: HEX SPACER MALE TO FEMALE M2.5 X 30MM; Chkd/date: MANIRAJA/190218; Crtd /date: MANIRAJA/190218; Distributor_name: DIGIKEY; Distributor_part_number: 732-10464-ND; Footprint Path: Y:\MIS_DATABASE\Library\ALTIUM_TOOL\PCB_FOOTPRINTS\Altium_Footprint_Lib.PcbLib; Height: 30.00MM; Library Path: Y:\MIS_DATABASE\Library\ALTIUM_TOOL\SCHEMATICS_PARTS\MS_MECHANICAL_Library.schlib; Mfr_name: WURTH ELECTRONICS; Mfr_part_number: 971300151; Mistral Part No: 160018020073-R; Package: SS; Part_type: MECHANICAL\SPACER; Project: TI_MAXIE_CPB; RoHS: RoHS; Datasheet: Y:\MIS_DATABASE\DATASHEETS\MISC\MECHANICAL\971XX0XX1.PDF
PCB1 = ACCESSORY_PROC062: ACCESSORIE AM65x EVM BARE PCB; Chkd/date: MANIRAJA/230718; Crtd /date: MANIRAJA/230718; Mfr_name: TEXAS INSTRUMENTS; Mfr_part_number: PROC062; Mistral Part No: FY180646000103; Part_type: ACCESSORIES; Project: TI_MAXIE_CPB
PCBA1 = ACCESSORY_PROC064: ACCESSORIE AM6x IDK APPLICATION CARD; Chkd/date: MANIRAJA/230718; Crtd /date: MANIRAJA/230718; Mfr_name: TEXAS INSTRUMENTS; Mfr_part_number: PROC064; Mistral Part No: FY180646000203; Part_type: ACCESSORIES; Project: TI_MAXIE_CPB
PCBA2 = ACCESSORY_PROC064: ACCESSORIE AM6x USB3/PCIE SERDES CARD; Chkd/date: MANIRAJA/230718; Crtd /date: MANIRAJA/230718; Mfr_name: TEXAS INSTRUMENTS; Mfr_part_number: PROC066; Mistral Part No: FY180646000603; Part_type: ACCESSORIES; Project: TI_MAXIE_CPB
PCBA3 = ACCESSORY_PROC064: ACCESSORIE AM6x PCIE-2 LANE SERDES CARD; Chkd/date: MANIRAJA/230718; Crtd /date: MANIRAJA/230718; Mfr_name: TEXAS INSTRUMENTS; Mfr_part_number: PROC067; Mistral Part No: FY180646000803; Part_type: ACCESSORIES; Project: TI_MAXIE_CPB

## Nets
DGND: B1.2(-) C113.1 C114.2 C115.2 C116.2 C151.2 C157.2 C158.2 C159.2 C164.2 C165.2 C167.2 C170.1 C180.2 C200.2 C201.2 C237.2 C238.2 C240.2 C241.2 C242.2 C373.2 C374.2 C375.2 C376.2 C377.2 C382.2 C383.2 C384.2 C386.2 C390.2 C391.2 C401.2 C408.2 C409.2 C410.2 C412.2 C420.2 C427.2 C428.2 C429.2 C431.2 C436.2 C437.2 C438.2 C441.2 C451.2 C452.2 C454.2 C456.2 C457.2 C458.2 C460.2 C461.2 C462.2 C463.2 C465.2 C467.2 C468.2 C469.2 C473.2 C476.2 C479.2 C482.2 C483.2 C484.2 C485.2 C486.2 C487.2 C488.2 C490.2 C491.2 C492.2 C493.2 C494.2 C496.2 C497.2 C498.2 C500.2 C502.2 C503.2 C509.2 C510.2 C511.2 C515.2 C516.2 C517.2 C518.2 C520.2 C524.2 C525.2 C526.2 C530.2 C531.2 C532.2 C533.2 C534.2 C535.2 C539.2 C541.2 C543.2 C550.2 C584.2 C587.2 C600.2 C602.2 C603.2 C637.2 D10.2(A) D12.2(A) D13.2(A) Q18.3(D) Q19.3(D) Q20.3(D) R765.2 SW5.3 SW5.4 SW5.5(GND) SW6.3 SW6.4 SW6.5(GND) SW7.3 SW7.4 SW7.5(GND) U52.4(GND) U91.4(VSS) U125.2(GND) Y3.2 Y3.4 Y4.2 Y4.4 ; also on sheet 13 14 15 16 17 18 19 20 21 22 23 24 25 26 27 28 29 30 31 32 33 34 35 36 37 38 39 40 41 42 43 44
VCC1V8: C237.1 R647.2 U125.3(VCCA) ; also on sheet 18 19 20 21 22 23 26 29 31 33 35 36 37 38 41 44
VCC3V3_IO: C238.1 C603.1 C637.1 R309.2 R318.2 R320.2 R321.2 R552.2 U52.8(VCC) U91.8(VCC) U125.7(VCCB) ; also on sheet 18 19 20 21 22 23 24 25 26 28 29 30 31 33 34 35 36 37 38 39 41 42 43 44
VDD_CORE: C373.1 C374.1 C376.1 C377.1 C382.1 C383.1 C390.1 C391.1 C431.1 C451.1 C469.1 C473.1 C476.1 C479.1 C484.1 C485.1 C486.1 C487.1 C488.1 C490.1 C491.1 C494.1 C500.1 C502.1 C503.1 C509.1 C510.1 C511.1 C516.1 C517.1 C518.1 C520.1 C531.1 C532.1 C533.1 C534.1 C539.1 C543.1 C550.1 U34.AA12(VDD_CORE) U34.J8(VDD_CORE) U34.J10(VDD_CORE) U34.J12(VDD_CORE) U34.J14(VDD_CORE) U34.J19(VDD_CORE) U34.K13(VDD_CORE) U34.L14(VDD_CORE) U34.L19(VDD_CORE) U34.M13(VDD_CORE) U34.N14(VDD_CORE) U34.P13(VDD_CORE) U34.P15(VDD_CORE) U34.P19(VDD_CORE) U34.R14(VDD_CORE) U34.R16(VDD_CORE) U34.R18(VDD_CORE) U34.T13(VDD_CORE) U34.T15(VDD_CORE) U34.T17(VDD_CORE) U34.T19(VDD_CORE) U34.U14(VDD_CORE) U34.U16(VDD_CORE) U34.U18(VDD_CORE) U34.V13(VDD_CORE) U34.V15(VDD_CORE) U34.V19(VDD_CORE) U34.W14(VDD_CORE) U34.W18(VDD_CORE) U34.Y11(VDD_CORE) U34.Y13(VDD_CORE) U34.Y15(VDD_CORE) ; also on sheet 13 26 39 41
VDD_MCU: C375.1 C384.1 C452.1 C457.1 C458.1 C468.1 C482.1 U34.N10(VDD_MCU) U34.P11(VDD_MCU) U34.R10(VDD_MCU) U34.R12(VDD_MCU) U34.T11(VDD_MCU) ; also on sheet 13 26
VDD_MPU: C437.1 C438.1 C456.1 C460.1 C461.1 C462.1 C463.1 C465.1 C467.1 C492.1 C496.1 C497.1 C498.1 C515.1 C524.1 C525.1 C526.1 C530.1 C535.1 U34.K9(VDD_MPU0) U34.K11(VDD_MPU0) U34.K16(VDD_MPU1) U34.K18(VDD_MPU1) U34.L8(VDD_MPU0) U34.L10(VDD_MPU0) U34.L17(VDD_MPU1) U34.M11(VDD_MPU0) U34.M16(VDD_MPU1) U34.M18(VDD_MPU1) U34.N17(VDD_MPU1) ; also on sheet 26 39 41
VDDSHV_SD_IO: C541.1 U34.H18(CAP_VDDSHV_SDIO) ; also on sheet 13 14 18
CAP_VDD_WKUP: C115.1 U34.V9(CAP_VDD_WKUP)
CAP_VDDA_1P8_IOLDO0: C170.2 U34.G19(CAP_VDDA_1P8_IOLDO0) ; also on sheet 13
CAP_VDDA_1P8_IOLDO1: C200.1 U34.Y19(CAP_VDDA_1P8_IOLDO1)
CAP_VDDA_1P8_IOLDO_WKUP: C113.2 U34.AA8(CAP_VDDA_1P8_IOLDO_WKUP) ; also on sheet 13
CAP_VDDA_1P8_SDIO: C180.1 R765.1 U34.J17(CAP_VDDA_1P8_SDIO) ; also on sheet 13
CAP_VDDAR_CORE0: C167.1 U34.P17(CAP_VDDAR_CORE0)
CAP_VDDAR_CORE1: C165.1 U34.V17(CAP_VDDAR_CORE1)
CAP_VDDAR_CORE2: C159.1 U34.W16(CAP_VDDAR_CORE2)
CAP_VDDAR_CORE3: C157.1 U34.M14(CAP_VDDAR_CORE3)
CAP_VDDAR_CORE4: C158.1 U34.L15(CAP_VDDAR_CORE4)
CAP_VDDAR_MCU: C116.1 U34.U10(CAP_VDDAR_MCU)
CAP_VDDAR_MPU0_0: C151.1 U34.M12(CAP_VDDAR_MPU0_0)
CAP_VDDAR_MPU0_1: C386.1 U34.N12(CAP_VDDAR_MPU0_1)
CAP_VDDAR_MPU2: C201.1 U34.N18(CAP_VDDAR_MPU1_0)
CAP_VDDAR_MPU3: C164.1 U34.N15(CAP_VDDAR_MPU1_1)
CAP_VDDAR_WKUP: C114.1 U34.Y10(CAP_VDDAR_WKUP)
Debounce_WARM_RST: C242.1 D13.1(K) Q20.2(S) R321.1 SW7.1 SW7.2 U52.6(3A)
Debounce_WKUP_GPIO0_13: C240.1 D12.1(K) Q18.2(S) R320.1 SW5.1 SW5.2 U52.3(2A)
Debounce_WKUP_GPIO0_27: C241.1 D10.1(K) Q19.2(S) R318.1 SW6.1 SW6.2 U52.1(1A)
OSC1_XI: R507.1 ; also on sheet 34
OSC1_XOUT: R511.1 ; also on sheet 34
SOC_I2C0_SCL: U91.6(SCL) ; also on sheet 33 34 37 38
SOC_I2C0_SDA: U91.5(SDA) ; also on sheet 33 34 37 38
SoC_VDDS_DDR: C408.1 C409.1 C410.1 C420.1 C427.1 C428.1 C429.1 C436.1 C441.1 C454.1 C483.1 C493.1 U34.G8(VDDS_DDR) U34.G10(VDDS_DDR) U34.G14(VDDS_DDR) U34.H7(VDDS_DDR) U34.H9(VDDS_DDR) U34.H13(VDDS_DDR) ; also on sheet 26
SoC_WARM_RESETZ: R309.1 U52.2(3Y) ; also on sheet 34
TEST_GPIO1: Q18.1(G) ; also on sheet 24
TEST_GPIO2: Q19.1(G) ; also on sheet 24
TEST_WARMRESETn: Q20.1(G) ; also on sheet 24
WKUP_GPIO0_13: U52.5(2Y) U125.8(B1)
WKUP_GPIO0_13_INTn: U125.5(A1) ; also on sheet 19
WKUP_GPIO0_27: U52.7(1Y) U125.1(B2)
WKUP_GPIO0_27_INTn: U125.4(A2) ; also on sheet 19
WKUP_LFOSC_RTC_XIN: R551.2 ; also on sheet 34
WKUP_LFOSC_XIN: R564.1 U91.1(X1)
WKUP_LFOSC_XOUT: R550.1 U91.2(X2)
WKUP_OSC0_XIN: R448.2 ; also on sheet 36
WKUP_OSC0_XIN_SOC: R448.1 R450.1 ; also on sheet 34
WKUP_OSC0_XOUT: R457.1 ; also on sheet 34
N16457366: C401.1 R450.2 R455.1 Y3.3
N16457370: C412.1 R455.2 R457.2 Y3.1
N16458713: C584.1 R507.2 R510.1 Y4.3
N16458717: C587.1 R510.2 R511.2 Y4.1
N16460347: C602.1 R563.1 R564.2 Y5.2
N16460351: C600.1 R550.2 R563.2 Y5.1
N16489740: R551.1 R552.1 U91.7(MFP)
N16493735: B1.1(+) U91.3(VBAT)
N23240225: R647.1 U125.6(OE)

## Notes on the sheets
sheet 1
- HARDWARE SCHEMATICS
- SCREWS
- JUMPERs
- STANDOFFs
- ASSEMBLY NOTES
- 1. All MSL components should be baked as per JEDEC standard.
  2. PCB should be baked at 120 degree for 8 hours.
  3. Board assembly must comply with workmanship standards.
  IPC-A-610 Class 2, unless otherwise specified.
  4. These assemblies are ESD sensitive, ESD precautions
  shall be observed.
  5. These assemblies must be clean and free from flux and
  all contaminants. Use of no clean flux is not acceptable.
  6. Provide serial numbers to the assembled boards for identification.
  7. The assembled board are wrapped in ESD Covers(individual) and
  packed securely before shipment.
- WASHER's
- FIDUCIALS
- RUBBER FEET
- SOCKET, PROCESSOR & HEATSINK AS ACCESSORIES
- BARE PCB
- ASSEMBLED PCB'S
- Processor
- LABELS
- LOGOs
- ORDERABLE PART NO
- Texas Intruments
- For Evaluation only; not FCC approved for resale
- WEEE Mark
- CE Mark
- Board Serial No.
- Orderable part number
- Variant
- Label Text
- 001
- TMDX654IDKEVM
- Assembly Revision
- 002
- TMDX654HSEVM
- 003
- TMDX654GPEVM
- 004
- TMDX654IDKEVM-S
- 005
- TMDX654GPEVM-S
sheet 2
- GPIO  MAPPING TABLE
sheet 3
- BLOCK DIAGRAM_XDS110
sheet 4
- SPI TREE
sheet 5
- I2C TREE
sheet 6
- POWER SEQUENCE
sheet 7
- POWER FLOW DIAGRAM
sheet 8
- BLOCK DIAGRAM_CP BOARD
sheet 9
- MAXWELL CUSTOMER PROCESSOR BOARD
- TABLE OF CONTENTS
- PAGE
- CONTENTS
- PAGE
- CONTENTS
- REV
- B
- 01
- TABLE OF CONTENTS
- 35
- CSI,GPMC/DSS INTERFACE
- VER
- 1.0
- 02
- REVISION HISTORY
- 36
- ETHERNET PHY  CLOCK GENERATOR
- 03
- BLOCK DIAGRAM_CP BOARD
- 37
- ETHERNET LEDs
- 04
- BLOCK DIAGRAM - XDS110
- 38
- TEST HEADER
- 05
- POWER FLOW DIAGRAM
- 39
- VOLTAGE SUPERVISOR
- 06
- POWER SEQUENCE
- 40
- PRE_REG and SERDES POWER SUPPLY
- 07
- GPIO MAPPING TABLE
- 41
- SoC POWER SUPPLY
- 08
- I2C TREE
- 42
- PERIPHERAL POWER SUPPLY
- 09
- SPI TREE
- 43
- OVER VOLTAGE  PROTECTION CKT AND TEST AUTOMATION POWER
- 10
- SoC CLOCK & RESET
- 44
- HARDWARE SCHEMATICS
- 11
- SoC POWER1
- 12
- SoC POWER2
- 13
- SoC POWER3
- 14
- SoC POWER4
- 15
- DDR4 DEVICES
- 16
- DDR4 ECC & TERMINATIONS
- 17
- eMMC FLASH AND SDCARD INTERFACE
- 18
- OSPI FLASH & SPI NOR FLASH
- 19
- EEPROM,PRESENCE DETECTION & TEMP SENSOR
- 20
- RGMII ETHERNET PHY - ICSSG PRG2_PRU0
- 21
- RGMII ETHERNET PHY - ICSSG PRG2_PRU1
- 22
- RGMII ETHERNET PHY - MCU
- 23
- TEST AUTOMATION
- 24
- BOOT MODE BUFFER & SWITCHES
- 25
- CURRENT MONITORING DEVICES
- 26
- XDS110  DEBUGGER
- 27
- JTAG BUFFER
- 28
- MIPI 60 PIN CONNECTOR
- 29
- USB 2.0 INTERFACE
- 30
- FT4232 LEVEL TRANSLATOR
- 31
- FT4232 UART TO USB BRIDGE
- 32
- APPLICATION BOARD CONNECTOR
- 33
- SOC_GENERAL & MCU GENERAL
- 34
- SERDES & DISPLAY INTERFACE
sheet 10
- REVISION HISTORY
- VER #
- DATE
- DESCRIPTION OF CHANGES
- AUTHOR
- REVIEWED  BY
- APPROVED  BY
- 0.1
- 7th APR 2021
- Drafted from "PROC062A_SCH" document.
- Mistral Design Team
- AJIT MB
- AJIT MB
- 0.2
- 7th APR 2021
- Changed SD card Load Switch to TPS22918DBVR
- Mistral Design Team
- AJIT MB
- AJIT MB
- 1.0
- 12th APR 2021
- Baselined
- Mistral Design Team
- AJIT MB
- AJIT MB
sheet 11
- SoC WARM_RST
- MCU_PUSH BUTTONS
- SoC CLOCK
sheet 12
- PROCESSOR POWER & DECAPS
